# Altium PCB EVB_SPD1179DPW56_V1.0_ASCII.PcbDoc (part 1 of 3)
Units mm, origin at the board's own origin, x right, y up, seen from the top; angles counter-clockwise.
Board outline 135 x 90 mm, 4 copper layers (Top Layer, GND, L3, Bottom Layer), stack 0.603 mm thick; 336 components, 177 nets, 814 pads, 1056 vias.
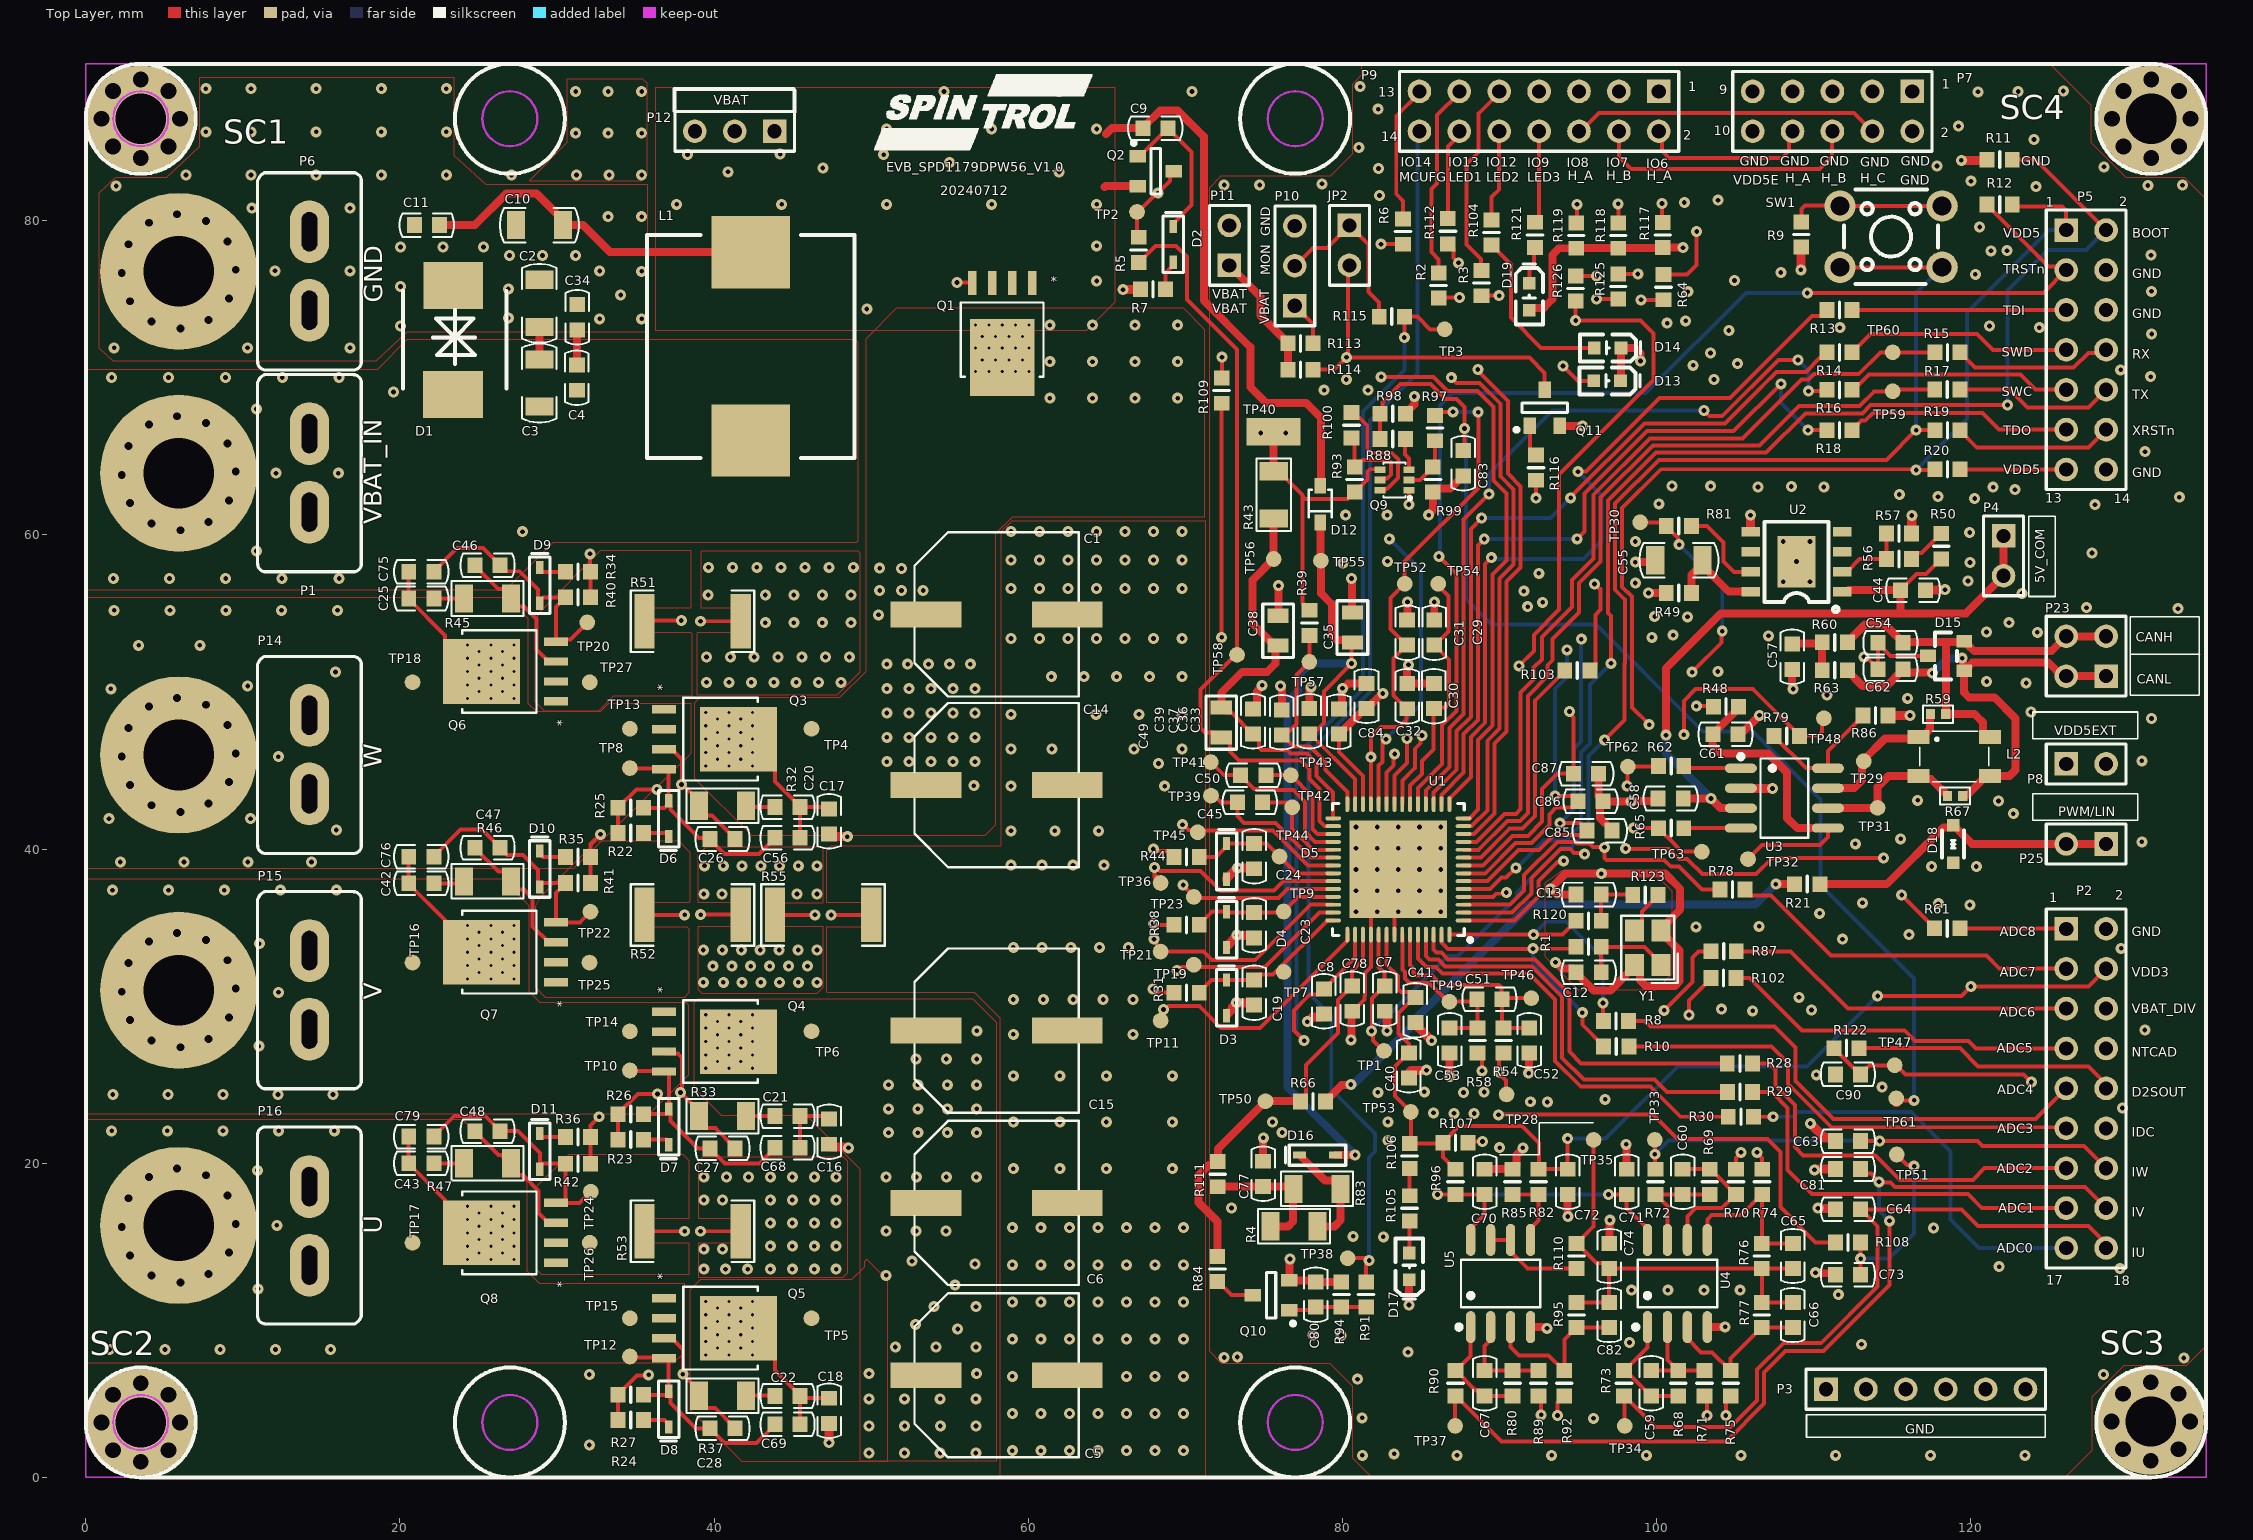
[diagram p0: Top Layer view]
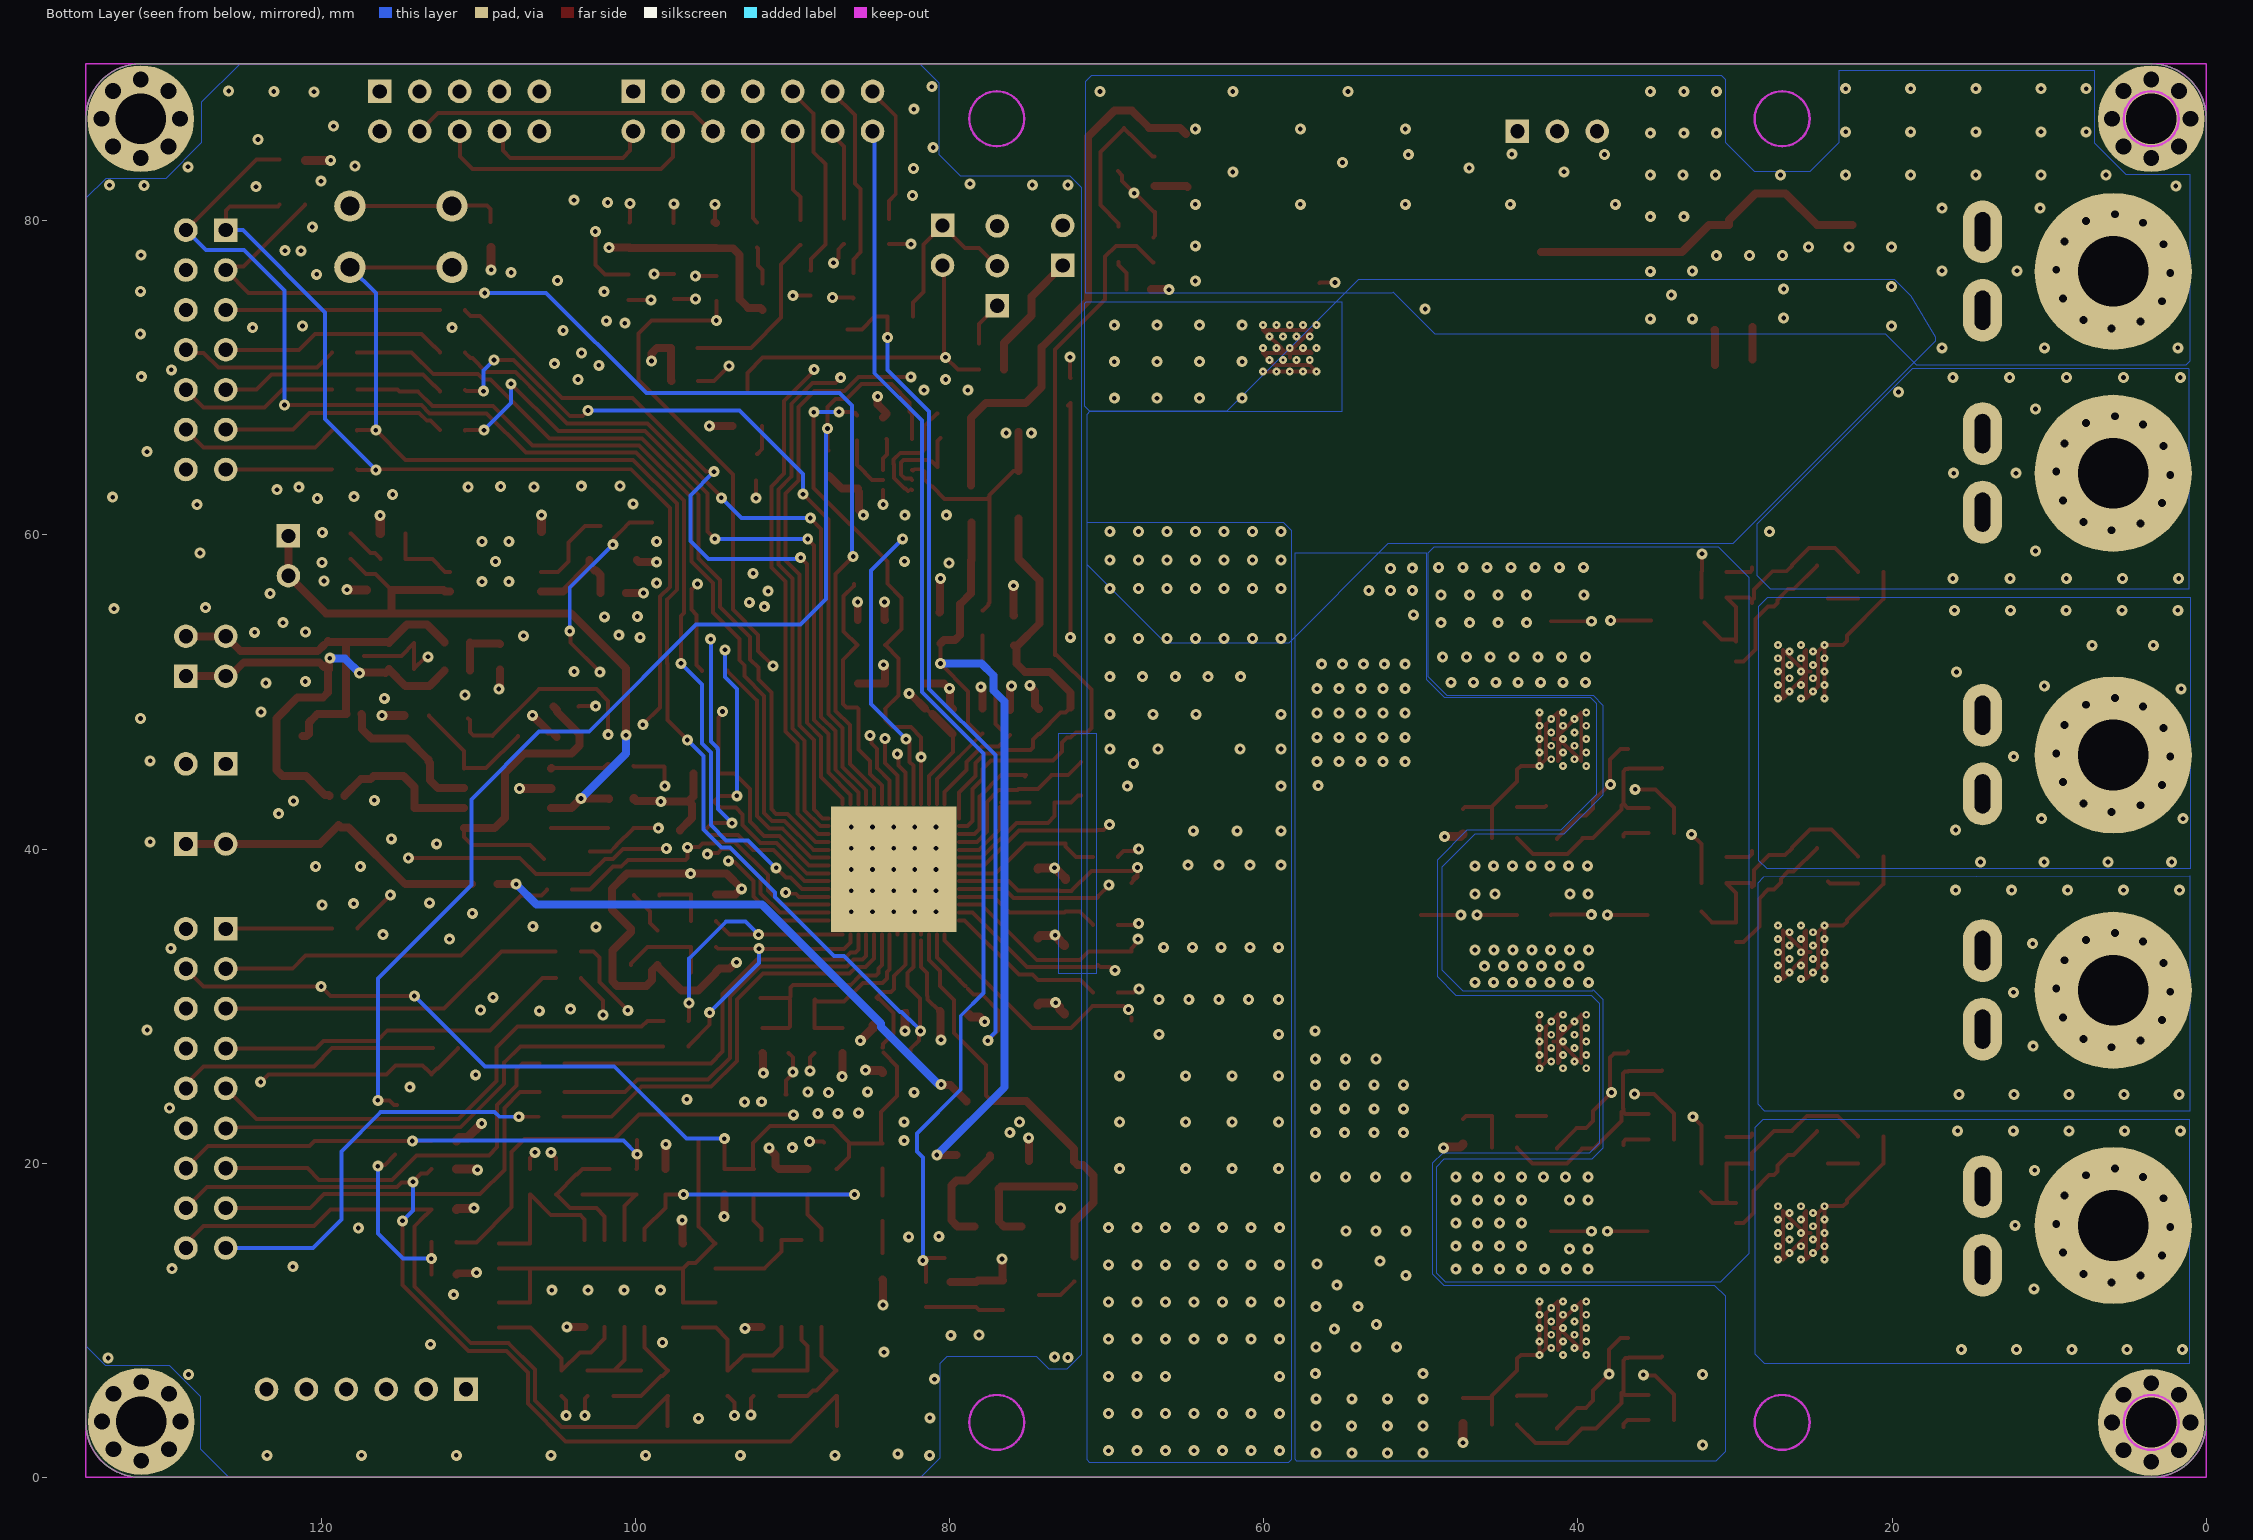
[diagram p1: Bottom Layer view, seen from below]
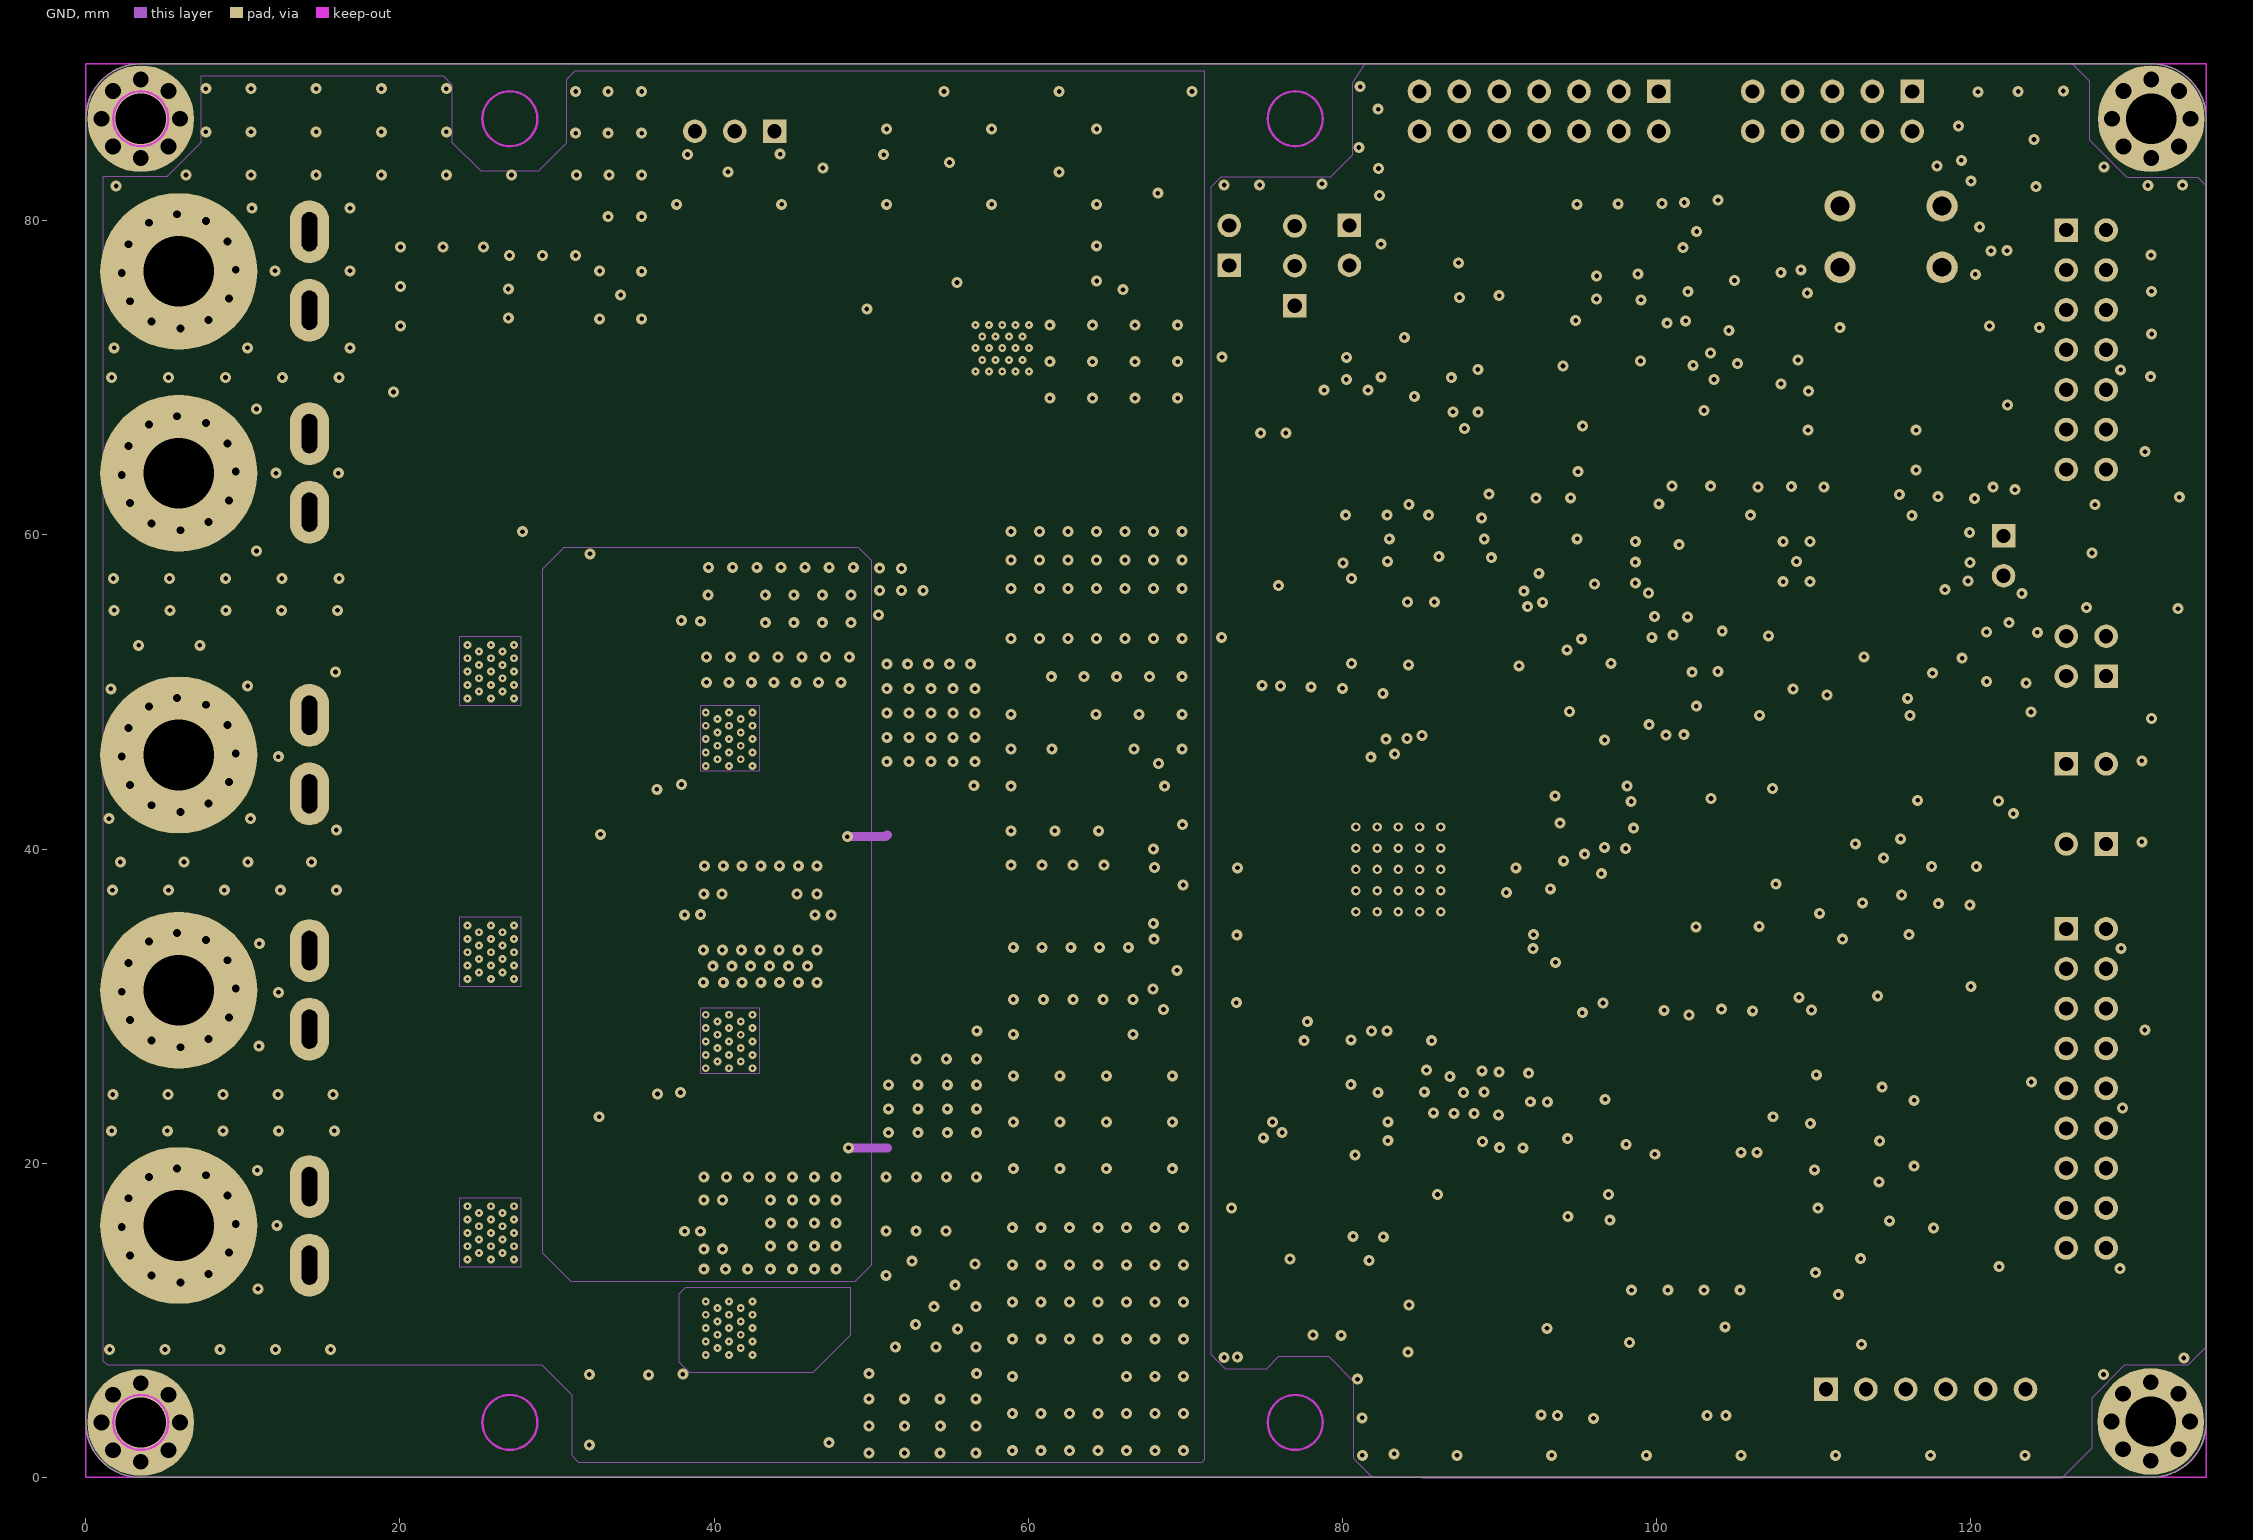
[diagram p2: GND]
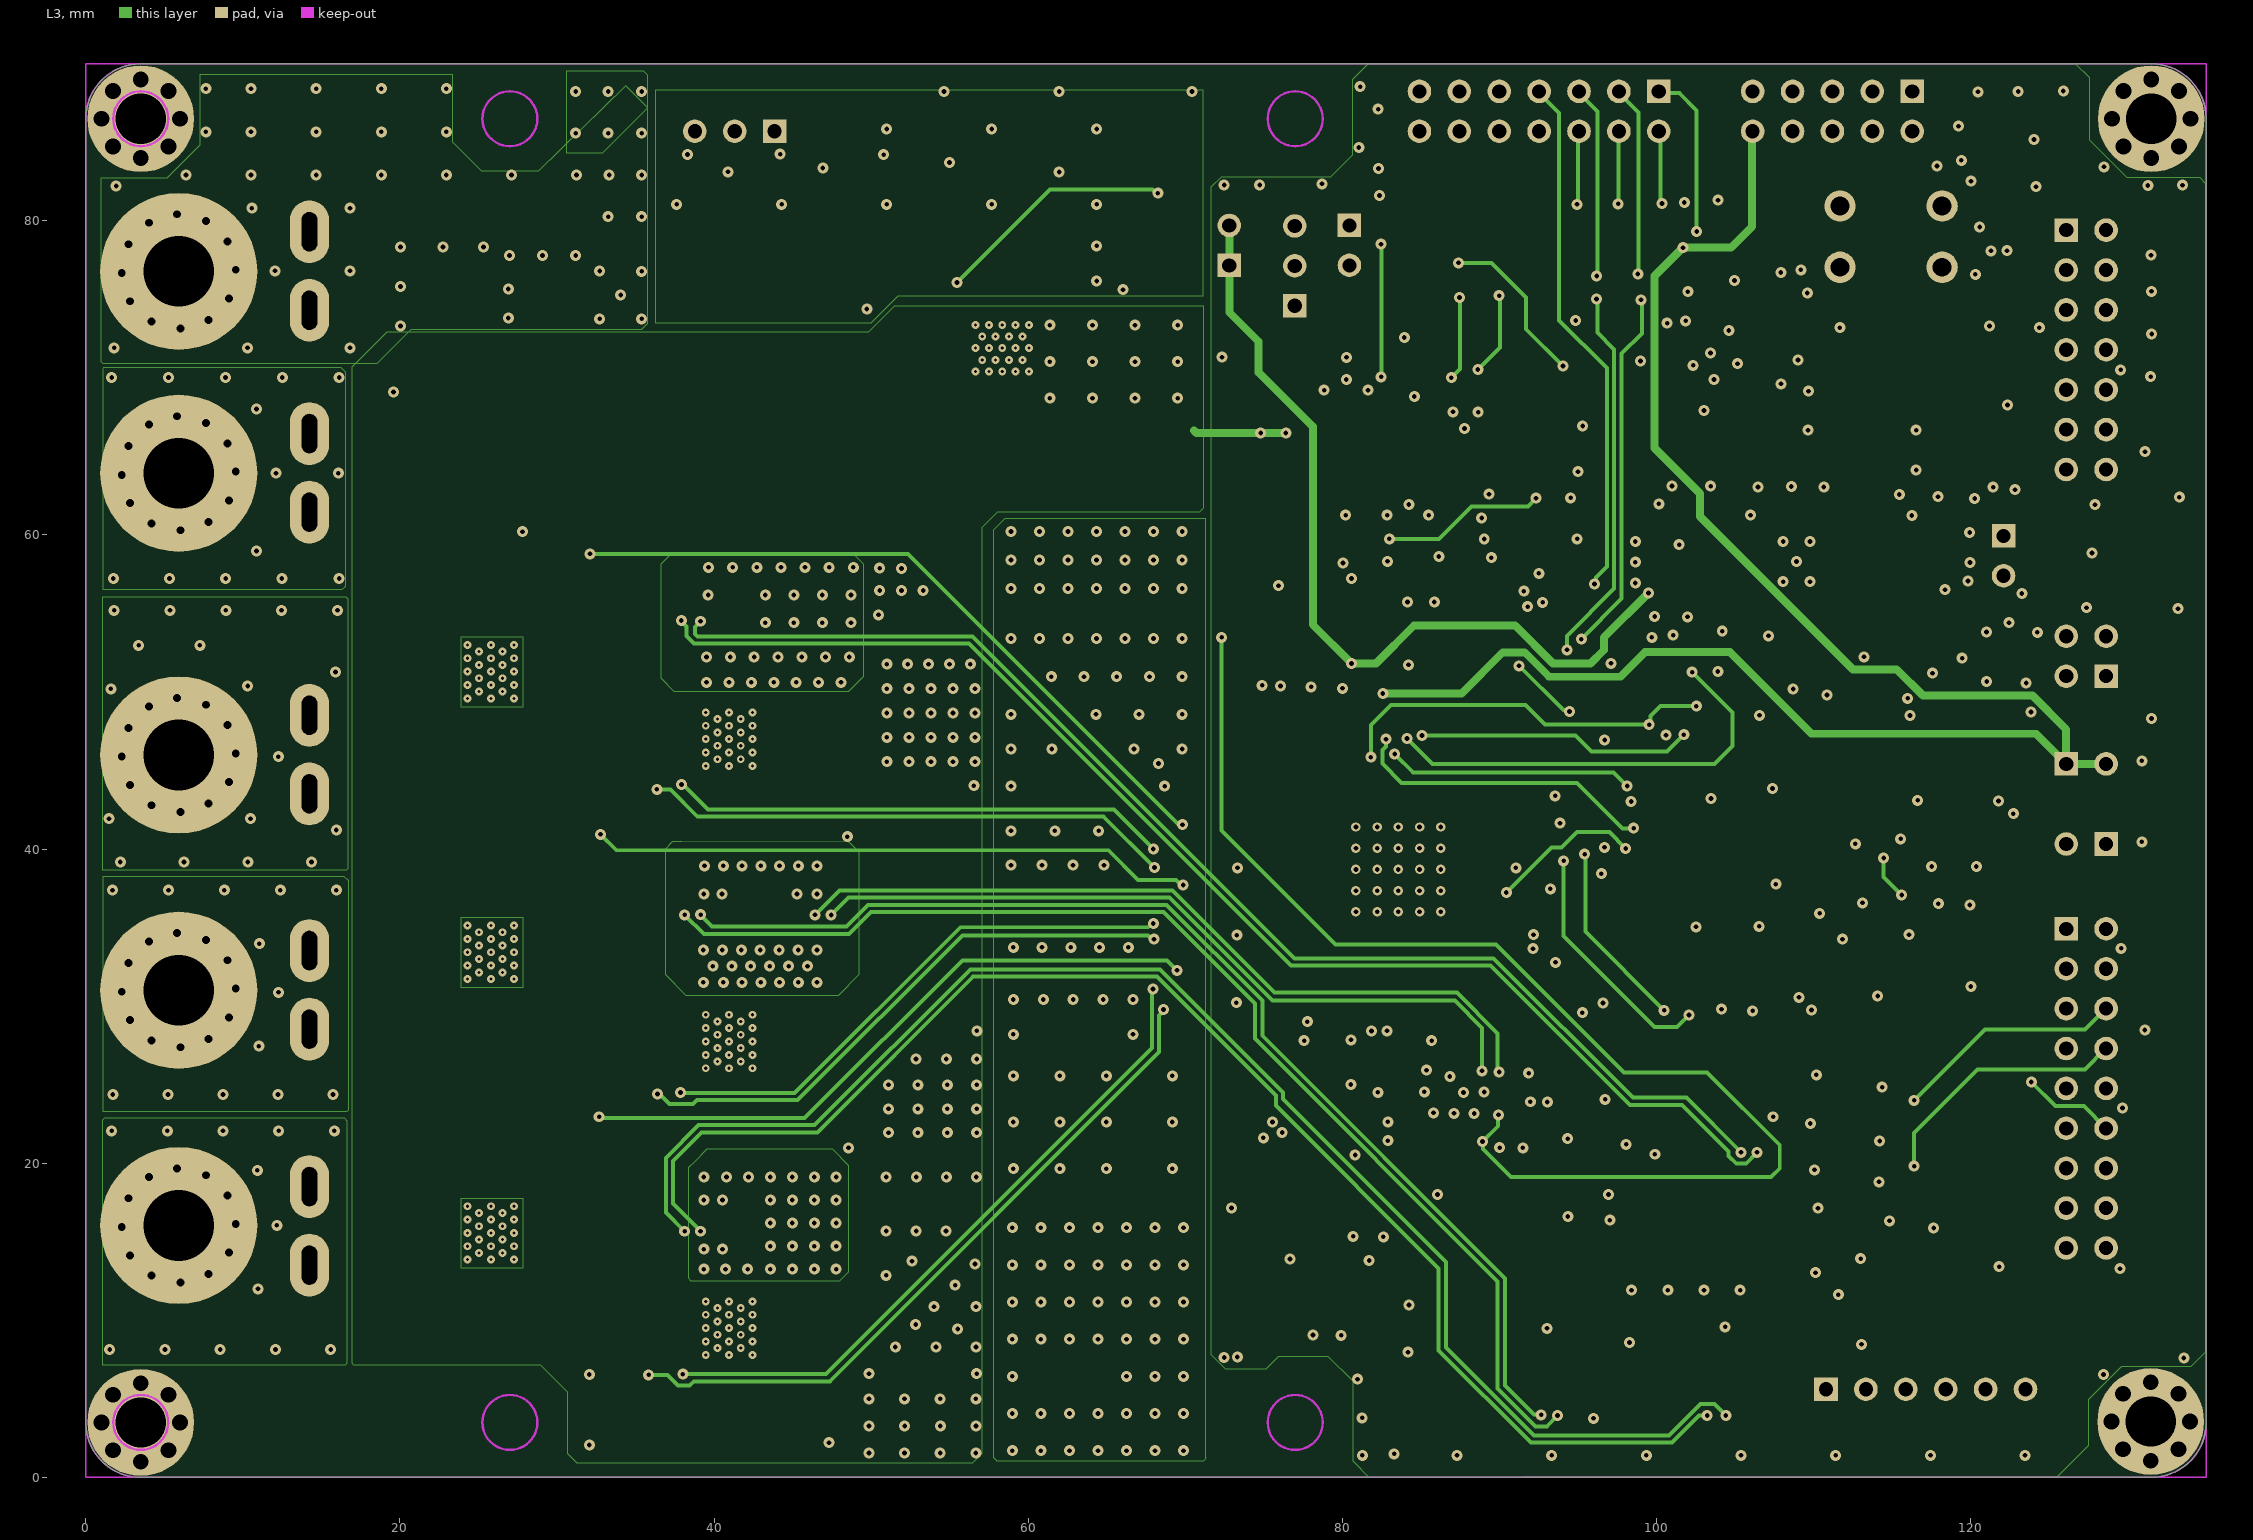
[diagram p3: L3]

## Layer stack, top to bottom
Top Solder: solder mask 0.0102, Solder Resist, Dk 3.5
Top Layer: signal copper 0.0356
Dielectric 2: prepreg 0.0711, PP-006, Dk 4.1
GND: signal copper 0.035
Dielectric 1: dielectric 0.32, FR-4, Dk 4.8
L3: signal copper 0.035
Dielectric 3: prepreg 0.0711, PP-006, Dk 4.1
Bottom Layer: signal copper 0.0356
Bottom Solder: solder mask 0.0102, Solder Resist, Dk 3.5

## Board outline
0,3.448 0,86.5 cw(c3.5,86.5) 3.448,90 131.5,90 cw(c131.5,86.5) 135,86.552 135,3.5 cw(c131.5,3.5) 131.552,0 3.5,0 cw(c3.5,3.5)

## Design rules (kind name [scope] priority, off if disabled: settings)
AssemblyTestPointUsage [All] p0: scope1count=1 scope1_0_kind=Board scope1_0_value=Board scope2count=1 scope2_0_kind=Board scope2_0_value=Board commentlength=0
AssemblyTestpoint [All] p0: scope1count=1 scope1_0_kind=Board scope1_0_value=Board scope2count=1 scope2_0_kind=Board scope2_0_value=Board commentlength=0
BoardOutlineClearance [All] p0: scope1count=1 scope1_0_kind=Board scope1_0_value=Board scope2count=1 scope2_0_kind=Board scope2_0_value=Board commentlength=0 gap=1
BoardOutlineClearance [All] p1: gap=1 ignorepadtopadclearanceinfootprint=FALSE
Clearance [All] p0: scope1count=1 scope1_0_kind=Board scope1_0_value=Board scope2count=1 scope2_0_kind=Board scope2_0_value=Board commentlength=0 gap=0.2
Clearance [All] p1: gap=0.2 ignorepadtopadclearanceinfootprint=FALSE except(0: Arc-Hole Track-Hole SMDPad-Hole THPad-Hole Via-Hole Fill-Hole Poly-Hole Region-Hole Text-Hole)
ComponentClearance [All] p0: scope1count=1 scope1_0_kind=Board scope1_0_value=Board scope2count=1 scope2_0_kind=Board scope2_0_value=Board commentlength=0 gap=0.05 collisioncheckmode=3
ComponentClearance [All] p1: gap=0.05 collisioncheckmode=3 verticalgap=0.05 showdistances=FALSE
DiffPairsRouting [All] p0: scope1count=1 scope1_0_kind=Board scope1_0_value=Board scope2count=1 scope2_0_kind=Board scope2_0_value=Board commentlength=0
FabricationTestPointUsage [All] p0: scope1count=1 scope1_0_kind=Board scope1_0_value=Board scope2count=1 scope2_0_kind=Board scope2_0_value=Board commentlength=0 valid=0 allowmultiple=FALSE
FabricationTestpoint [All] p0: scope1count=1 scope1_0_kind=Board scope1_0_value=Board scope2count=1 scope2_0_kind=Board scope2_0_value=Board commentlength=0 side=3 testpointundercomponent=TRUE minsize=1.016 maxsize=2.54 preferedsize=1.524 minholesize=0 maxholesize=1.016 preferedholesize=0.813 testpointgrid=0.025
FanoutControl Fanout_Default [All] p0: scope1count=1 scope1_0_kind=Board scope1_0_value=Board scope2count=1 scope2_0_kind=Board scope2_0_value=Board commentlength=30 // Fanout_Default (Default Rule)
FanoutControl Fanout_Small [All] p0 off: scope1count=1 scope1_0_kind=Board scope1_0_value=Board scope2count=1 scope2_0_kind=Board scope2_0_value=Board commentlength=84 // Protel DXP Scope 1 Expression Was: (CompPinCount < 5)   Fanout_Small (Default Rule)
FanoutControl Fanout_SOIC [All] p0 off: scope1count=1 scope1_0_kind=Board scope1_0_value=Board scope2count=1 scope2_0_kind=Board scope2_0_value=Board commentlength=71 // Protel DXP Scope 1 Expression Was: IsSOIC   Fanout_SOIC (Default Rule)
FanoutControl Fanout_LCC [All] p0 off: scope1count=1 scope1_0_kind=Board scope1_0_value=Board scope2count=1 scope2_0_kind=Board scope2_0_value=Board commentlength=69 // Protel DXP Scope 1 Expression Was: IsLCC   Fanout_LCC (Default Rule)
FanoutControl Fanout_BGA [All] p0 off: scope1count=1 scope1_0_kind=Board scope1_0_value=Board scope2count=1 scope2_0_kind=Board scope2_0_value=Board commentlength=69 // Protel DXP Scope 1 Expression Was: IsBGA   Fanout_BGA (Default Rule)
Height [All] p0: scope1count=1 scope1_0_kind=Board scope1_0_value=Board scope2count=1 scope2_0_kind=Board scope2_0_value=Board commentlength=0
HoleSize [All] p0: scope1count=1 scope1_0_kind=Board scope1_0_value=Board scope2count=1 scope2_0_kind=Board scope2_0_value=Board commentlength=0 absolutevalues=TRUE maxlimit=10 minlimit=0.025 maxpercent=80.000 minpercent=20.000
HoleSize [All] p1: absolutevalues=TRUE maxlimit=10 minlimit=0.025 maxpercent=80.000 minpercent=20.000
HoleToHoleClearance [All] p0: scope1count=1 scope1_0_kind=Board scope1_0_value=Board scope2count=1 scope2_0_kind=Board scope2_0_value=Board commentlength=0
HoleToHoleClearance [All] p1: gap=0 allowstackedmicrovias=TRUE
LayerPairs [All] p0: scope1count=1 scope1_0_kind=Board scope1_0_value=Board scope2count=1 scope2_0_kind=Board scope2_0_value=Board commentlength=0 enforce=TRUE
MinimumSolderMaskSliver [All] p0: scope1count=1 scope1_0_kind=Board scope1_0_value=Board scope2count=1 scope2_0_kind=Board scope2_0_value=Board commentlength=0
MinimumSolderMaskSliver [All] p1: minsoldermaskwidth=0
NetAntennae [All] p0: scope1count=1 scope1_0_kind=Board scope1_0_value=Board scope2count=1 scope2_0_kind=Board scope2_0_value=Board commentlength=0
PasteMaskExpansion [All] p0: scope1count=1 scope1_0_kind=Board scope1_0_value=Board scope2count=1 scope2_0_kind=Board scope2_0_value=Board commentlength=0 expansion=0
PlaneClearance [All] p0: scope1count=1 scope1_0_kind=Board scope1_0_value=Board scope2count=1 scope2_0_kind=Board scope2_0_value=Board commentlength=0 clearance=0.508
PlaneConnect [All] p0: scope1count=1 scope1_0_kind=Board scope1_0_value=Board scope2count=1 scope2_0_kind=Board scope2_0_value=Board commentlength=0 planeconnectstyle=Relief reliefexpansion=0.508 reliefentries=4 reliefconductorwidth=0.254 reliefairgap=0.254
PolygonConnect GND [All] p0 off: scope1count=1 scope1_0_kind=Board scope1_0_value=Board scope2count=1 scope2_0_kind=Board scope2_0_value=Board commentlength=57 connectstyle=Direct reliefconductorwidth=0.5 reliefentries=4 polygonreliefangle="90 Angle" // Protel DXP Scope 2 Expression Was: All And  Not IsVia
PolygonConnect [All] p0: scope1count=1 scope1_0_kind=Board scope1_0_value=Board scope2count=1 scope2_0_kind=Board scope2_0_value=Board commentlength=0 connectstyle=Direct reliefconductorwidth=0.254 reliefentries=4 polygonreliefangle="45 Angle"
PolygonConnect GND [IsNamedPolygon('GND') And InNet('GND') vs All And  Not IsVia] p1: connectstyle=Direct reliefconductorwidth=0.5 reliefentries=4 polygonreliefangle="90 Angle" airgapwidth=0.3
PolygonConnect [All] p2: connectstyle=Direct reliefconductorwidth=0.254 reliefentries=4 polygonreliefangle="45 Angle" airgapwidth=0.254
RoutingCorners [All] p0: scope1count=1 scope1_0_kind=Board scope1_0_value=Board scope2count=1 scope2_0_kind=Board scope2_0_value=Board commentlength=0 cornerstyle=45-Degree minsetback=2.54 maxsetback=2.54
RoutingLayers [All] p0: scope1count=1 scope1_0_kind=Board scope1_0_value=Board scope2count=1 scope2_0_kind=Board scope2_0_value=Board commentlength=0 top layer=Automatic mid layer 1=Automatic mid layer 2=Automatic bottom layer=Automatic
RoutingPriority [All] p0: scope1count=1 scope1_0_kind=Board scope1_0_value=Board scope2count=1 scope2_0_kind=Board scope2_0_value=Board commentlength=0
RoutingTopology [All] p0: scope1count=1 scope1_0_kind=Board scope1_0_value=Board scope2count=1 scope2_0_kind=Board scope2_0_value=Board commentlength=0 topology=Shortest
RoutingVias [All] p0: scope1count=1 scope1_0_kind=Board scope1_0_value=Board scope2count=1 scope2_0_kind=Board scope2_0_value=Board commentlength=0 holewidth=0.711 width=1.27 viastyle="Through Hole" minholewidth=0.711 minwidth=1.27 maxholewidth=0.711 maxwidth=1.27
RoutingVias [All] p1: holewidth=0.711 width=1.27 viastyle="Through Hole" minholewidth=0.711 minwidth=1.27 maxholewidth=0.711 maxwidth=1.27
ShortCircuit [All] p0: scope1count=1 scope1_0_kind=Board scope1_0_value=Board scope2count=1 scope2_0_kind=Board scope2_0_value=Board commentlength=0 allowed=FALSE
SilkToBoardRegionClearance [All] p0: scope1count=1 scope1_0_kind=Board scope1_0_value=Board scope2count=1 scope2_0_kind=Board scope2_0_value=Board commentlength=0
SilkToSilkClearance [All] p0 off: scope1count=1 scope1_0_kind=Board scope1_0_value=Board scope2count=1 scope2_0_kind=Board scope2_0_value=Board commentlength=0
SilkToSilkClearance [All] p1 off: silktosilkclearance=0
SilkToSolderMaskClearance [All] p0 off: scope1count=1 scope1_0_kind=Board scope1_0_value=Board scope2count=1 scope2_0_kind=Board scope2_0_value=Board commentlength=44 // Protel DXP Scope 1 Expression Was: IsPad
SilkToSolderMaskClearance [IsPad] p1: minsilkscreentomaskgap=0 clearancetoexposedcopper=TRUE
SolderMaskExpansion [All] p0: scope1count=1 scope1_0_kind=Board scope1_0_value=Board scope2count=1 scope2_0_kind=Board scope2_0_value=Board commentlength=0 expansion=0.102
SolderMaskExpansion [All] p1: expansion=0.102 istentingtop=FALSE
UnRoutedNet [All] p0: scope1count=1 scope1_0_kind=Board scope1_0_value=Board scope2count=1 scope2_0_kind=Board scope2_0_value=Board commentlength=0
UnpouredPolygon [All] p0: scope1count=1 scope1_0_kind=Board scope1_0_value=Board scope2count=1 scope2_0_kind=Board scope2_0_value=Board commentlength=0
Width [All] p0: scope1count=1 scope1_0_kind=Board scope1_0_value=Board scope2count=1 scope2_0_kind=Board scope2_0_value=Board commentlength=0 maxlimit=2.54 minlimit=0.203 preferedwidth=0.254
Width [All] p1: maxlimit=2.54 minlimit=0.203 preferedwidth=0.254
24 further rules are at their usual default settings.

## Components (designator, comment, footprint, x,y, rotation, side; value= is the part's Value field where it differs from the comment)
C1 "EEHZK1E471P" CAP-SMD_BD10.0-L10.3-W10.3-FD 57.988,54.947 r0 top
C2 "CAP" C1206 28.88,74.752 r270 top
C3 "CAP" C1206 28.88,69.672 r270 top
C4 "CAP" C0603 31.267,70.015 r270 top
C5 "EEHZK1E471P" CAP-SMD_BD10.0-L10.3-W10.3-FD 57.988,6.502 r0 top
C6 "EEHZK1E471P" CAP-SMD_BD10.0-L10.3-W10.3-FD 57.988,17.475 r0 top
C7 "CAP" C0603 82.703,30.48 r90 top
C8 "CAP" C0603 78.829,30.306 r90 top
C9 "CAP" C0603 68.097,85.903 r180 top
C10 "CAP" C1206 28.88,79.731 r180 top
C11 "CAP" C0603 21.717,79.731 r0 top
C12 "CAP" C0603 95.682,32.156 r0 top
C13 "CAP" C0603 95.682,37.109 r0 top
C14 "EEHZK1E471P" CAP-SMD_BD10.0-L10.3-W10.3-FD 57.988,44.076 r0 top
C15 "EEHZK1E471P" CAP-SMD_BD10.0-L10.3-W10.3-FD 57.988,28.448 r0 top
C16 "CAP" C0603 47.32,22.012 r90 top
C17 "CAP" C0603 47.32,41.764 r90 top
C18 "CAP" C0603 47.32,4.242 r90 top
C19 "NC" C0603 74.381,30.864 r90 top
C20 "CAP" C0603 44.679,42.679 r0 top
C21 "CAP" C0603 44.679,23.003 r0 top
C22 "CAP" C0603 44.679,5.182 r0 top
C23 "NC" C0603 74.381,35.154 r90 top
C24 "NC" C0603 74.381,39.551 r90 top
C25 "CAP" C0603 21.361,55.956 r180 top
C26 "CAP" C0603 40.538,40.647 r180 top
C27 "CAP" C0603 40.538,20.946 r180 top
C28 "CAP" C0603 40.538,3.124 r180 top
C29 "CAP" C0603 85.852,53.784 r270 top
C30 "CAP" C0603 85.833,49.742 r270 top
C31 "CAP" C0603 84.122,53.784 r270 top
C32 "CAP" C0603 84.128,49.737 r270 top
C33 "CAP" C0603 79.785,48.122 r270 top
C34 "CAP" C0603 31.293,73.863 r270 top
C35 "CAP" 0805R 80.642,55.06 r270 top
C36 "CAP" C0603 77.9,48.147 r270 top
C37 "CAP" C0603 76.144,48.068 r270 top
C38 "CAP" 0805R 75.908,54.861 r270 top
C39 "CAP" C0603 74.312,48.134 r270 top
C40 "CAP" C0603 84.242,26.228 r90 top
C41 "CAP" C0603 84.653,29.753 r90 top
C42 "CAP" C0603 21.361,37.819 r180 top
C43 "CAP" C0603 21.361,19.998 r180 top
C44 "CAP" C0603 116.332,56.49 r180 top
C45 "CAP" C0603 74.115,42.977 r180 top
C46 "CAP" C0603 25.578,58.064 r0 top
C47 "CAP" C0603 25.578,40.08 r0 top
C48 "CAP" C0603 25.578,22.047 r0 top
C49 "CAP" 0805R 72.292,47.109 r90 top
C50 "CAP" C0603 74.33,44.704 r0 top
C51 "CAP" C0603 89.367,30.437 r0 top
C52 "CAP" C0603 91.907,27.821 r90 top
C53 "CAP" C0603 86.827,27.821 r90 top
C54 "CAP" C0603 114.897,53.137 r0 top
C55 "CAP" C1206 101.422,58.395 r0 top
C56 "NC" C0603 44.679,40.723 r180 top
C57 "CAP" C0603 108.636,52.248 r90 top
C58 "CAP" C0603 100.904,43.222 r0 top
C59 "CAP" C0603 99.662,5.994 r90 top
C60 "CAP" C0603 101.662,18.821 r90 top
C61 "CAP" C0603 104.394,47.32 r180 top
C62 "CAP" C0603 114.897,51.46 r0 top
C63 "CAP" C0603 112.192,21.412 r0 top
C64 "CAP" C0603 112.192,17.069 r0 top
C65 "CAP" C0603 108.687,14.097 r90 top
C66 "CAP" C0603 108.687,10.338 r270 top
C67 "CAP" C0603 89.057,5.994 r90 top
C68 "NC" C0603 44.679,20.996 r180 top
C69 "NC" C0603 44.679,3.378 r180 top
C70 "CAP" C0603 89.057,18.821 r270 top
C71 "CAP" C0603 98.106,18.821 r270 top
C72 "CAP" C0603 94.345,18.821 r90 top
C73 "CAP" C0603 112.192,12.903 r0 top
C74 "CAP" C0603 96.987,14.097 r270 top
C75 "NC" C0603 21.361,57.658 r0 top
C76 "NC" C0603 21.361,39.521 r0 top
C77 "CAP" C0603 74.955,19.329 r270 top
C78 "CAP" C0603 80.629,30.48 r90 top
C79 "NC" C0603 21.361,21.7 r0 top
C80 "CAP" C0603 78.313,11.637 r270 top
C81 "CAP" C0603 112.192,19.634 r0 top
C82 "CAP" C0603 96.987,10.338 r270 top
C83 "CAP" C0603 87.701,64.568 r90 top
C84 "CAP" C0603 81.538,49.75 r270 top
C85 "CAP" C0603 96.381,41.18 r0 top
C86 "CAP" C0603 95.808,43.042 r180 top
C87 "CAP" C0603 95.521,44.803 r0 top
C90 "CAP" C0603 112.192,25.654 r0 top
D1 "" SMC/DO-214AB/Bidirect 23.495,72.593 r90 top
D2 "DIODE" SODFL2513X100/SOD323F/SC-90 69.24,78.508 r270 top
D3 "NC" SODFL2513X100/SOD323F/SC-90 72.628,30.531 r270 top
D4 "NC" SODFL2513X100/SOD323F/SC-90 72.628,34.874 r270 top
D5 "NC" SODFL2513X100/SOD323F/SC-90 72.628,39.218 r270 top
D6 "" SODFL2513X100/SOD323F/SC-90 37.109,41.942 r90 top
D7 "" SODFL2513X100/SOD323F/SC-90 37.109,22.317 r90 top
D8 "" SODFL2513X100/SOD323F/SC-90 37.109,4.343 r90 top
D9 "" SODFL2513X100/SOD323F/SC-90 28.905,56.794 r270 top
D10 "" SODFL2513X100/SOD323F/SC-90 28.905,38.737 r270 top
D11 "" SODFL2513X100/SOD323F/SC-90 28.905,20.76 r270 top
D12 "DIODE" SOD-323_L1.8-W1.3-LS2.5-RD 78.595,61.971 r90 top
D13 "D_LED_0603" LED0603-R-RD 96.86,69.809 r180 top
D14 "D_LED_0603" LED0603-R-RD 96.892,71.905 r180 top
D15 "PESD1CAN,215" SOT-23_L2.9-W1.3-P1.90-LS2.4-BR 118.44,52.299 r0 top
D16 "" SODFL2513X100/SOD323F/SC-90 78.419,20.523 r0 top
D17 "D_LED_0603" LED0603-R-RD 84.261,13.437 r90 top
D18 "TVS" SOD-323_L1.7-W1.3-LS2.5-BI 118.897,40.327 r90 top
D19 "D_LED_0603" LED0603-R-RD 91.905,75.171 r270 top
JP2 "open" HDR1X2 80.452,79.708 r270 top
L1 "1uH 40A" IND-SMD_L12.6-W13.5 42.342,72.009 r90 top
L2 "ACT45B-510-2P-TL003" IND-SMD_4P-L4.5-W3.2-TL 118.949,45.897 r0 top
P1 "P_CON-1PIN" CON_63X08_P1 14.24,66.457 r270 top
P2 "Header 9X2" HDR2X9 126.086,34.925 r270 top
P3 "Header 6" HDR1X6 110.795,5.613 r0 top
P4 "" HDR1X2 122.098,59.944 r270 top
P5 "Header 7X2" HDR2X7 126.086,79.41 r270 top
P6 "P_CON-1PIN" CON_63X08_P1 14.24,79.309 r270 top
P7 "Header 5X2" HDR2X5 116.282,88.244 r180 top
P8 "" HDR1X2 126.086,45.425 r0 top
P9 "Header 7X2" HDR2X7 100.149,88.244 r180 top
P10 "Header 3" HDR1X3 76.974,74.596 r90 top
P11 "" HDR1X2 72.803,77.168 r90 top
P12 "Header 3" HDR1X3 43.855,85.704 r180 top
P14 "P_CON-1PIN" CON_63X08_P1 14.24,48.518 r270 top
P15 "P_CON-1PIN" CON_63X08_P1 14.24,33.542 r270 top
P16 "P_CON-1PIN" CON_63X08_P1 14.24,13.517 r90 top
P23 "Header 2X2" HDR2X2 128.626,51.013 r90 top
P25 "Header 2" HDR1X2 128.626,40.327 r180 top
Q1 "SQJ138EP" PowerPAK_SO-8L_3_VIS 58.344,72.441 r180 top
Q2 "NPN" SOT95P240X110-3/SOT23/TO-236 68.123,83.16 r0 top
Q3 "SQJ138EP" PowerPAK_SO-8L_3_VIS 40.411,46.997 r270 top
Q4 "SQJ138EP" PowerPAK_SO-8L_3_VIS 40.411,27.748 r270 top
Q5 "SQJ138EP" PowerPAK_SO-8L_3_VIS 40.411,9.5 r270 top
Q6 "SQJ138EP" PowerPAK_SO-8L_3_VIS 26.333,51.308 r90 top
Q7 "SQJ138EP" PowerPAK_SO-8L_3_VIS 26.333,33.439 r90 top
Q8 "SQJ138EP" PowerPAK_SO-8L_3_VIS 26.333,15.57 r90 top
Q9 "BC847BPN,115" SOT-363_L2.0-W1.3-P0.65-LS2.1-TL 83.312,63.5 r180 top
Q10 "NPN" SOT95P240X110-3/SOT23/TO-236 75.461,11.601 r180 top
Q11 "MOSFET_N-CH" SOT95P240X110-3/SOT23/TO-236 92.885,68.097 r90 top
R1 "NC" R0603 95.682,33.782 r180 top
R2 "RES" R0603 86.133,75.888 r270 top
R3 "RES" R0603 88.857,76.033 r270 top
R4 "" R1206 76.922,15.983 r0 top
R5 "RES" R0603 67.031,78.156 r90 top
R6 "RES" R0603 83.861,79.312 r270 top
R7 "RES" R0603 67.945,75.641 r0 top
R8 "RES" R0603 97.429,29.064 r180 top
R9 "RES" R0603 109.22,79.129 r270 top
R10 "RES" R0603 97.439,27.433 r180 top
R11 "RES" R0603 121.852,83.897 r0 top
R12 "RES" R0603 121.852,81.045 r0 top
R13 "RES" R0603 111.658,74.32 r180 top
R14 "RES" R0603 111.658,71.628 r180 top
R15 "RES" R0603 118.529,71.628 r0 top
R16 "RES" R0603 111.658,69.24 r180 top
R17 "RES" R0603 118.516,69.266 r0 top
R18 "RES" R0603 111.658,66.667 r180 top
R19 "RES" R0603 118.529,66.667 r0 top
R20 "RES" R0603 118.529,64.186 r180 top
R21 "RES" R0603 109.601,37.77 r180 top
R22 "" R0603 34.696,41.028 r180 top
R23 "" R0603 34.696,21.504 r180 top
R24 "" R0603 34.696,3.658 r180 top
R25 "" R0603 34.696,42.628 r180 top
R26 "" R0603 34.696,23.13 r180 top
R27 "" R0603 34.696,5.258 r180 top
R28 "RES" R0603 105.308,26.352 r180 top
R29 "RES" R0603 105.321,24.536 r180 top
R30 "RES" R0603 105.372,22.962 r180 top
R31 "RES" R0603 70.088,30.861 r0 top
R32 "RES" R1206 40.538,42.755 r180 top
R33 "RES" R1206 40.538,23.003 r180 top
R34 "" R0603 31.344,57.658 r0 top
R35 "" R0603 31.344,39.496 r0 top
R36 "" R0603 31.344,21.674 r0 top
R37 "RES" R1206 40.538,5.207 r180 top
R38 "RES" R0603 70.088,35.179 r0 top
R39 "" R0603 77.911,54.407 r90 top
R40 "" R0603 31.344,56.032 r0 top
R41 "" R0603 31.344,37.845 r0 top
R42 "" R0603 31.344,19.972 r0 top
R43 "RES" R1206 75.625,62.56 r270 top
R44 "RES" R0603 70.088,39.497 r0 top
R45 "RES" R1206 25.578,55.956 r0 top
R46 "RES" R1206 25.578,37.946 r0 top
R47 "RES" R1206 25.578,19.998 r0 top
R48 "RES" R0603 104.419,49.073 r180 top
R49 "RES" R0603 101.422,56.312 r0 top
R50 "RES" R0603 118.135,59.284 r270 top
R51 "RES" R2512 38.633,54.508 r180 top
R52 "RES" R2512 38.633,35.814 r180 top
R53 "RES" R2512 38.633,15.672 r180 top
R54 "RES" R0603 90.256,27.821 r90 top
R55 "RES" R2512 46.939,35.814 r180 top
R56 "RES" R0603 115.443,58.471 r0 top
R57 "RES" R0603 115.443,60.096 r180 top
R58 "RES" R0603 88.605,27.821 r90 top
R59 "NC" R0402 117.929,48.594 r0 top
R60 "RES" R0603 111.354,53.162 r0 top
R61 "RES" R0603 118.512,34.954 r180 top
R62 "RES" R0603 100.937,45.296 r180 top
R63 "RES" R0603 111.354,51.384 r0 top
R64 "RES" R0603 100.448,75.775 r270 top
R65 "RES" R0603 100.937,41.336 r180 top
R66 "磁珠" R0603 78.13,23.927 r180 top
R67 "NC" R0402 119.012,43.387 r0 top
R68 "RES" R0603 101.389,5.994 r90 top
R69 "RES" R0603 103.389,18.821 r90 top
R70 "RES" R0603 105.057,18.821 r90 top
R71 "RES" R0603 103.057,5.994 r270 top
R72 "RES" R0603 99.935,18.821 r270 top
R73 "RES" R0603 97.935,5.994 r90 top
R74 "RES" R0603 106.725,18.821 r90 top
R75 "RES" R0603 104.725,5.994 r270 top
R76 "RES" R0603 106.705,14.097 r90 top
R77 "RES" R0603 106.705,10.338 r270 top
R78 "RES" R0603 104.834,37.424 r180 top
R79 "RES" R0603 108.294,47.201 r180 top
R80 "RES" R0603 90.84,5.994 r90 top
R81 "RES" R0603 101.422,60.579 r0 top
R82 "RES" R0603 92.491,18.821 r270 top
R83 "" R1206 78.384,18.364 r0 top
R84 "NC" R0603 72.044,13.275 r270 top
R85 "RES" R0603 90.84,18.821 r90 top
R86 "RES" R0603 113.949,48.514 r180 top
R87 "RES" R0603 104.281,33.496 r180 top
R88 "RES" R0603 83.21,66.116 r0 top
R89 "RES" R0603 92.491,5.994 r270 top
R90 "RES" R0603 87.208,5.994 r90 top
R91 "RES" R0603 81.513,11.637 r90 top
R92 "RES" R0603 94.133,5.994 r270 top
R93 "RES" R0603 80.781,63.528 r90 top
R94 "RES" R0603 79.939,11.637 r270 top
R95 "RES" R0603 94.904,10.338 r270 top
R96 "" R0603 87.208,18.821 r270 top
R97 "RES" R0603 85.902,66.801 r270 top
R98 "RES" R0603 83.21,67.716 r0 top
R99 "RES" R0603 85.765,63.528 r90 top
R100 "RES" R0603 80.579,66.987 r90 top
R102 "RES" R0603 104.267,31.797 r180 top
R103 "RES" R0603 94.96,51.369 r180 top
R104 "RES" R0603 89.499,79.263 r270 top
R105 "RES" R0603 84.287,17.132 r270 top
R106 "RES" R0603 84.287,20.46 r90 top
R107 "RES" R0603 87.198,21.311 r180 top
R108 "RES" R0603 112.192,14.961 r0 top
R109 "NTC" R0603 72.314,69.19 r90 top
R110 "RES" R0603 94.904,14.097 r270 top
R111 "NC" R0603 72.069,19.304 r270 top
R112 "RES" R0603 86.72,79.339 r270 top
R113 "RES" R0603 77.344,72.199 r180 top
R114 "" R0603 77.337,70.524 r0 top
R115 "RES" R0603 83.149,73.903 r180 top
R116 "RES" R0603 92.336,64.283 r90 top
R117 "RES" R0603 100.397,79.099 r270 top
R118 "RES" R0603 97.57,79.058 r270 top
R119 "RES" R0603 94.889,79.056 r270 top
R120 "NC" R0603 95.682,35.433 r180 top
R121 "RES" R0603 92.263,79.109 r270 top
R122 "RES" R0603 112.09,27.33 r0 top
R123 "RES" R0603 99.289,37.084 r180 top
R125 "RES" R0603 97.563,75.819 r270 top
R126 "RES" R0603 94.856,75.694 r270 top
SC1 "SCREW" "SCREW_HOLE_Φ3_plated_wo keepout" 3.5,86.5 r0 top (schematic designator SC?)
SC2 "SCREW" "SCREW_HOLE_Φ3_plated_wo keepout" 3.5,3.5 r0 top (schematic designator SC?)
SC3 "SCREW" "SCREW_HOLE_Φ3_plated_wo keepout" 131.472,3.555 r0 top (schematic designator SC?)
SC4 "SCREW" "SCREW_HOLE_Φ3_plated_wo keepout" 131.5,86.5 r0 top (schematic designator SC?)
SW1 "TS-1095PD-A6B2-D2" KEY-TH_4P-L6.0-W6.0-P3.90-LS6.5 114.935,78.994 r0 top
TP1 "TEST-Point" TP-1.0 82.652,27.153 r0 top
TP2 "TEST-Point" TP-1.0 66.929,80.569 r0 top
TP3 "TEST-Point" TP-1.0 86.511,73.094 r0 top
TP4 "TEST-Point" TP-1.0 46.203,47.66 r0 top
TP5 "TEST-Point" TP-1.0 46.203,10.135 r0 top
TP6 "TEST-Point" TP-1.0 46.203,28.397 r0 top
TP7 "TEST-Point" TP-1.0 76.26,32.182 r0 top
TP8 "TEST-Point" TP-1.0 34.646,45.161 r90 top
TP9 "TEST-Point" TP-1.0 76.26,36.03 r0 top
TP10 "TEST-Point" TP-1.0 34.646,25.908 r90 top
TP11 "TEST-Point" TP-1.0 68.428,29.083 r90 top
TP12 "TEST-Point" TP-1.0 34.646,7.696 r90 top
TP13 "TEST-Point" TP-1.0 34.646,47.66 r90 top
TP14 "TEST-Point" TP-1.0 34.646,28.397 r90 top
TP15 "TEST-Point" TP-1.0 34.646,10.135 r90 top
TP16 "TEST-Point" TP-1.0 20.803,32.779 r180 top
TP17 "TEST-Point" TP-1.0 20.803,14.935 r90 top
TP18 "TEST-Point" TP-1.0 20.803,50.622 r90 top
TP19 "TEST-Point" TP-1.0 70.545,32.639 r180 top
TP20 "TEST-Point" TP-1.0 31.928,54.432 r0 top
TP21 "TEST-Point" TP-1.0 68.428,33.477 r180 top
TP22 "TEST-Point" TP-1.0 32.131,36.017 r90 top
TP23 "TEST-Point" TP-1.0 70.545,36.957 r180 top
TP24 "TEST-Point" TP-1.0 32.156,18.186 r0 top
TP25 "TEST-Point" TP-1.0 32.069,32.779 r90 top
TP26 "TEST-Point" TP-1.0 32.08,14.935 r90 top
TP27 "TEST-Point" TP-1.0 32.08,50.622 r90 top
TP28 "TEST-Point" TP-1.0 90.454,24.383 r90 top
TP29 "TEST-Point" TP-1.0 113.191,45.589 r90 top
TP30 "TEST-Point" TP-1.0 98.958,60.808 r270 top
TP31 "TEST-Point" TP-1.0 114.075,42.626 r90 top
TP32 "TEST-Point" TP-1.0 105.828,39.366 r90 top
TP33 "TEST-Point" TP-1.0 99.898,21.488 r180 top
TP34 "TEST-Point" TP-1.0 97.974,3.277 r180 top
TP35 "TEST-Point" TP-1.0 95.996,21.488 r180 top
TP36 "TEST-Point" TP-1.0 68.428,37.846 r270 top
TP37 "TEST-Point" TP-1.0 87.182,3.277 r90 top
TP38 "TEST-Point" TP-1.0 80.336,13.957 r180 top
TP39 "TEST-Point" TP-1.0 71.637,43.409 r270 top
TP40 "TEST-SMD" TEST-SMD_L2.7-W1.0 75.625,66.573 r0 top
TP41 "TEST-Point" TP-1.0 71.623,45.544 r90 top
TP42 "TEST-Point" TP-1.0 76.806,42.671 r90 top
TP43 "TEST-Point" TP-1.0 76.725,44.707 r90 top
TP44 "TEST-Point" TP-1.0 76,39.531 r90 top
TP45 "TEST-Point" TP-1.0 70.79,41.072 r90 top
TP46 "TEST-Point" TP-1.0 92.034,30.513 r90 top
TP47 "TEST-Point" TP-1.0 115.164,26.238 r90 top
TP48 "TEST-Point" TP-1.0 110.663,48.331 r90 top
TP49 "TEST-Point" TP-1.0 86.818,30.284 r90 top
TP50 "TEST-Point" TP-1.0 75.108,23.952 r90 top
TP51 "TEST-Point" TP-1.0 115.3,20.559 r180 top
TP52 "TEST-Point" TP-1.0 83.972,56.896 r180 top
TP53 "TEST-Point" TP-1.0 84.363,23.266 r270 top
TP54 "TEST-Point" TP-1.0 86.106,56.896 r180 top
TP55 "TEST-Point" TP-1.0 78.638,58.369 r180 top
TP56 "TEST-Point" TP-1.0 75.625,58.471 r180 top
TP57 "TEST-Point" TP-1.0 77.902,51.918 r90 top
TP58 "TEST-Point" TP-1.0 73.295,52.365 r180 top
TP59 "TEST-Point" TP-1.0 115.037,69.147 r90 top
TP60 "TEST-Point" TP-1.0 115.037,71.628 r90 top
TP61 "TEST-Point" TP-1.0 115.265,24.13 r90 top
TP62 "TEST-Point" TP-1.0 98.18,45.255 r90 top
TP63 "TEST-Point" TP-1.0 102.892,39.834 r90 top
U1 "SPD1179" QFN-56-0.5_B 87.716,35.46 r180 top
U2 "LDO钰泰" ESOP-8_L4.9-W3.9-P1.27-LS6.0-BL-EP 108.915,58.293 r90 top
U3 "TJA1044GT/3" SOIC-8_L4.9-W3.9-P1.27-LS6.0-BL 108.144,43.242 r270 top
U4 "AD8542ARZ-REEL7" SOIC-8_L4.9-W3.9-P1.27-LS6.0-BL 101.332,12.344 r0 top
U5 "AD8542ARZ-REEL7" SOIC-8_L4.9-W3.9-P1.27-LS6.0-BL 90.078,12.344 r0 top
Y1 "32MHz" CRYSTAL-SMD_4P-L3.2-W2.5-BL 99.441,33.731 r90 top

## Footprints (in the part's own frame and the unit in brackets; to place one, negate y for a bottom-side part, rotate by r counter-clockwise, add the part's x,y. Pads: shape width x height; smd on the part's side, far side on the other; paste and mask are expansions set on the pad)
0805R [mm]
  rect 0.9x1.35 smd: 1(0,0) 2(1.9,0)
  silkscreen extent -0.75,-0.97 2.65,0.97
C0603 [mm]
  rect 0.95x1 smd: 1(-0.8,0) 2(0.8,0)
  silkscreen extent -1.73,-0.75 1.73,0.75
C1206 [mm]
  rect 1.15x1.8 smd: 1(-1.5,0) 2(1.5,0)
  silkscreen extent -2.51,-1.1 2.51,1.1
CAP-SMD_BD10.0-L10.3-W10.3-FD [mm]
  rect 4.5x1.65 smd: 1(-4.5,0) 2(4.5,0)
  silkscreen extent -5.23,-5.23 5.23,5.23
CON_63X08_P1 [mm] "Insert terminal"
  oval 4x2.5 hole 1 slot 2.5 at 0 deg: 1(0,0) 1(5,0)
  silkscreen extent -3.75,-3.3 8.8,3.3
CRYSTAL-SMD_4P-L3.2-W2.5-BL [mm]
  rect 1.4x1.2 smd: 1(-1.1,-0.85) 2(1.1,-0.85) 3(1.1,0.85) 4(-1.1,0.85)
  silkscreen extent -2.26,-1.91 2.03,1.68
ESOP-8_L4.9-W3.9-P1.27-LS6.0-BL-EP [mm]
  rect 0.6x1.2 smd: 1(-1.905,-2.908) 2(-0.635,-2.908) 3(0.635,-2.908) 4(1.905,-2.908) 5(1.905,2.908) 6(0.635,2.908) 7(-0.635,2.908) 8(-1.905,2.908)
  rect 3.3x2.4 smd: 9(0,0)
  silkscreen extent -3.2,-2.67 2.55,2.05
HDR1X2 [mm] "Connector; Header; 2 Position"
  rect 1.5x1.5 hole 0.9: 1(0,0)
  round 1.5 hole 0.9: 2(2.54,0)
  silkscreen extent -1.27,-1.27 3.81,1.27
HDR1X3 [mm] "Connector; Header; 3 Position"
  rect 1.5x1.5 hole 0.9: 1(0,0)
  round 1.5 hole 0.9: 2(2.54,0) 3(5.08,0)
  silkscreen extent -1.27,-1.27 6.35,1.27
HDR1X6 [mm] "Connector; Header; 6 Position"
  rect 1.5x1.5 hole 0.9: 1(0,0)
  round 1.5 hole 0.9: 2(2.54,0) 3(5.08,0) 4(7.62,0) 5(10.16,0) 6(12.7,0)
  silkscreen extent -1.27,-1.27 13.97,1.27
HDR2X2 [mm] "Connector; Header; 2x2 Position"
  rect 1.5x1.5 hole 0.9: 1(0,0)
  round 1.5 hole 0.9: 2(0,2.54) 3(2.54,0) 4(2.54,2.54)
  silkscreen extent -1.27,-1.27 3.81,3.81
HDR2X5 [mm] "Connector; Header; 5x2 Position"
  rect 1.5x1.5 hole 0.9: 1(0,0)
  round 1.5 hole 0.9: 2(0,2.54) 3(2.54,0) 4(2.54,2.54) 5(5.08,0) 6(5.08,2.54) 7(7.62,0) 8(7.62,2.54) 9(10.16,0) 10(10.16,2.54)
  silkscreen extent -1.27,-1.27 11.43,3.81
HDR2X7 [mm] "Connector; Header; 7x2 Position"
  rect 1.5x1.5 hole 0.9: 1(0,0)
  round 1.5 hole 0.9: 2(0,2.54) 3(2.54,0) 4(2.54,2.54) 5(5.08,0) 6(5.08,2.54) 7(7.62,0) 8(7.62,2.54) 9(10.16,0) 10(10.16,2.54) 11(12.7,0) 12(12.7,2.54) 13(15.24,0) 14(15.24,2.54)
  silkscreen extent -1.27,-1.27 16.51,3.81
HDR2X9 [mm] "Connector; Header; 9x2 Position"
  rect 1.5x1.5 hole 0.9: 1(0,0)
  round 1.5 hole 0.9: 2(0,2.54) 3(2.54,0) 4(2.54,2.54) 5(5.08,0) 6(5.08,2.54) 7(7.62,0) 8(7.62,2.54) 9(10.16,0) 10(10.16,2.54) 11(12.7,0) 12(12.7,2.54) 13(15.24,0) 14(15.24,2.54) 15(17.78,0) 16(17.78,2.54) 17(20.32,0) 18(20.32,2.54)
  silkscreen extent -1.27,-1.27 21.59,3.81
IND-SMD_4P-L4.5-W3.2-TL [mm]
  rect 1.4x0.899 smd mask+0: 1(-2.281,1.25) 2(-2.281,-1.25) 3(2.281,-1.25) 4(2.281,1.25)
  silkscreen extent -2.2,-1.6 2.2,1.6
IND-SMD_L12.6-W13.5 [mm]
  rect 4.6x5 smd paste+0 mask+0: 1(-6,0) 2(6,0)
  silkscreen extent -7.1,-6.6 7.1,6.6
KEY-TH_4P-L6.0-W6.0-P3.90-LS6.5 [mm]
  round 2 hole 1.2: 1(-3.25,1.95) 2(3.25,1.95) 3(-3.25,-1.95) 4(3.25,-1.95)
  silkscreen extent -3,-3 3,3
LED0603-R-RD [mm]
  rect 0.8x0.8 smd: 1(0.851,0) 2(-0.851,0)
  silkscreen extent -2.08,-0.86 1.77,0.86
PowerPAK_SO-8L_3_VIS [mil]
  rect 21x60 smd paste+0 mask+0: 1(-75,-142) 2(-25,-142) 3(25,-142) 4(75,-142)
  rect 162x193 smd paste+0 mask+0: 5(0,44.5)
  Top Layer lines w10: 0,44.5 0,34 ; 0,21.75 0,29.75 ; -67.25,80 -33.75,80 -0.25,80 0,80 33.25,80 66.75,80 50,63.25 16.5,63.25 0,63.25 -17,63.25 -38,63.25 -50.5,50.75 -67.25,34 -33.75,34 -0.25,34 0,34 ; 0,34 33.25,34 54.25,34 50,29.75 33.25,29.75 0,29.75 ; 0,34 0,29.75 ; 0,29.75 -0.25,29.75 -13.01,29.75 -27.5,15.25 -50.5,-7.75 -67.25,-24.5 -33.75,-24.5 -0.25,-24.5 0,-24.5 33.25,-24.5 54.25,-24.5 43.75,-14 4,25.75 0,29.75 ; 0,29.75 0,29.75 ; 0,29.75 0,29.75 ; 0,29.75 0,29.75
  silkscreen extent -104,-93 104,93
QFN-56-0.5_B [mm] "按高发封装修改意见"
  oval 1x0.25 smd: 1(0,0) 2(0,-0.5) 3(0,-1) 4(0,-1.5) 5(0,-2) 6(0,-2.5) 7(0,-3) 8(0,-3.5) 9(0,-4) 10(0,-4.5) 11(0,-5) 12(0,-5.5) 13(0,-6) 14(0,-6.5) 29(8.3,-6.5) 30(8.3,-6) 31(8.3,-5.5) 32(8.3,-5) 33(8.3,-4.5) 34(8.3,-4) 35(8.3,-3.5) 36(8.3,-3) 37(8.3,-2.5) 38(8.3,-2) 39(8.3,-1.5) 40(8.3,-1) 41(8.3,-0.5) 42(8.3,0)
  oval 0.25x1 smd: 15(0.9,-7.4) 16(1.4,-7.4) 17(1.9,-7.4) 18(2.4,-7.4) 19(2.9,-7.4) 20(3.4,-7.4) 21(3.9,-7.4) 22(4.4,-7.4) 23(4.9,-7.4) 24(5.4,-7.4) 25(5.9,-7.4) 26(6.4,-7.4) 27(6.9,-7.4) 28(7.4,-7.4) 43(7.4,0.9) 44(6.9,0.9) 45(6.4,0.9) 46(5.9,0.9) 47(5.4,0.9) 48(4.9,0.9) 49(4.4,0.9) 50(3.9,0.9) 51(3.4,0.9) 52(2.9,0.9) 53(2.4,0.9) 54(1.9,0.9) 55(1.4,0.9) 56(0.9,0.9)
  rect 6.2x6.2 smd: 57(4.15,-3.25)
  rect 8x8 smd far side: 57(4.15,-3.25)
  silkscreen extent -0.55,-7.45 8.35,1.36
R0402 [mm] "Resistor,Chip;1.00mm L X 0.50mm W"
  rect 0.59x0.64 smd: 1(-0.48,0) 2(0.48,0)
  silkscreen extent -0.95,-0.55 0.95,0.55
R0603 [mm] "Resistor,Chip;1.60mm L X 0.80mm W"
  rect 0.95x1 smd: 1(-0.8,0) 2(0.8,0)
  silkscreen extent 0,-0.5 0,0.5
R1206 [mm] "Chip Resistor; Body 3.2 x 1.6 mm (LxW typ)"
  rect 1.15x1.8 smd: 1(-1.5,0) 2(1.5,0)
  silkscreen extent -2.3,-1.1 2.3,1.1
R2512 [mm]
  rect 1.283x3.456 smd: 1(-3.066,0) 2(3.066,0)
  silkscreen extent -3.94,-1.96 3.94,1.96
"SCREW_HOLE_Φ3_plated_wo keepout" [mm] "with Spring  of Φ6.8mm"
  round 1 hole 1: 1(-2.5,0) 1(-1.768,-1.768) 1(-1.768,1.768) 1(0,-2.5) 1(0,2.5) 1(1.768,-1.768) 1(1.768,1.768) 1(2.5,0)
  round 6.8 hole 3.2: 1(0,0)
SMC/DO-214AB/Bidirect [mm]
  rect 3x3.8 smd: 1(3.301,0.102) 2(-3.649,0.112)
  silkscreen extent -3.27,-3.3 2.93,3.3
SOD-323_L1.7-W1.3-LS2.5-BI [mil]
  rect 31.5x31.5 smd mask+0: 1(-47.4,0) 2(47.4,0)
  silkscreen extent -34,-27 33,28
SOD-323_L1.8-W1.3-LS2.5-RD [mm]
  rect 1x0.75 smd: 1(-1.173,0) 2(1.173,0)
  silkscreen extent -0.85,-0.73 0.9,0.73
SODFL2513X100/SOD323F/SC-90 [mm]
  rect 0.84x0.46 smd: 1(-1.14,0) 2(1.14,0)
  silkscreen extent -2.03,-0.65 1.8,0.65
SOIC-8_L4.9-W3.9-P1.27-LS6.0-BL [mm]
  oval 0.588x2.045 smd: 1(-1.905,-2.773) 2(-0.635,-2.773) 3(0.635,-2.773) 4(1.905,-2.773) 5(1.905,2.773) 6(0.635,2.773) 7(-0.635,2.773) 8(-1.905,2.773)
  silkscreen extent -2.8,-2.92 2.53,1.52
SOT95P240X110-3/SOT23/TO-236 [mm]
  rect 1.05x0.8 smd: 1(-1.15,0.95) 2(-1.15,-0.95) 3(1.15,0)
  silkscreen extent -1.52,-1.45 0.3,1.92
SOT-23_L2.9-W1.3-P1.90-LS2.4-BR [mm]
  rect 1x0.8 smd mask+0: 1(1.15,-0.95) 2(1.15,0.95) 3(-1.15,0)
  silkscreen extent -0.7,-1.5 0.7,1.5
SOT-363_L2.0-W1.3-P0.65-LS2.1-TL [mm]
  rect 0.7x0.42 smd: 1(-0.92,0.65) 2(-0.92,0) 3(-0.92,-0.65) 4(0.92,-0.65) 5(0.92,0) 6(0.92,0.65)
  silkscreen extent -1.09,-1.1 0.7,1.24
TEST-SMD_L2.7-W1.0 [mm]
  rect 3.43x1.78 smd: 1(0,0)
TP-1.0 [mm]
  round 1 smd: 1(0,0)

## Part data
C1 C5 C6 C14 C15: library part CE_50V_220uF_10*10, "Capacitor polarized"
C2 C3 C10 C35 C38 C55: library part C_1206_10%_1, "MLCC"
C4 C7 C8 C9 C11 C12 C13 C16 C17 C18 C19 C20 C21 C22 C23 C24 C25 C26 C27 C28 C29 C30 C31 C32 C33 C34 C36 C37 C39 C40 C41 C42 C43 C44 C45 C46 C47 C48 C49 C50 C51 C52 C53 C54 C56 C57 C58 C59 C60 C61 C62 C63 C64 C65 C66 C67 C68 C69 C70 C71 C72 C73 C74 C75 C76 C77 C78 C79 C80 C81 C82 C83 C84 C85 C86 C87 C90: library part C_0603_10%_1, "MLCC"
D1: library part D_TVS_SMC, "TVS Bidirectional"
D2 D3 D4 D5 D6 D7 D8 D9 D10 D11 D16: library part D_1N4148WS, "Diode SOD323"
D12: library part D_SMA, "Diode"
D15: library part D_PESD1CAN,215
D18: library part D_ESD_BI_SOD323, "ESD TVS Bidirectional"
JP2: library part Jumper, "Jumper Wire"
L1: library part L_SER2000
L2: library part L_ACT45B-510-2P-TL003
P1 P6 P14 P15 P16: "Insert terminal,快接端子 6.3mm*0.8厚 插片"
P2: "Header, 9-Pin, Dual row"
P3: "Header, 6-Pin"
P4 P8 P11: library part "Header 2", "Header, 2-Pin"
P5 P9: "Header, 7-Pin, Dual row"
P7: "Header, 5-Pin, Dual row"
P10 P12: "Header, 3-Pin"
P23: "Header, 2-Pin, Dual row"
P25: "Header, 2-Pin"
Q1 Q3 Q4 Q5 Q6 Q7 Q8: library part Q_N_DFN-8L_5*6, "N-CHANNEL"
Q2 Q10: library part Q_8050
Q9: library part Q_BC847BPN,115
Q11: library part Q_BSS138, "N-CHANNEL"
R1 R2 R3 R5 R6 R7 R8 R9 R10 R11 R12 R13 R14 R15 R16 R17 R18 R19 R20 R21 R22 R23 R24 R25 R26 R27 R28 R29 R30 R31 R34 R35 R36 R38 R39 R40 R41 R42 R44 R48 R49 R50 R54 R56 R57 R58 R60 R61 R62 R63 R64 R65 R66 R68 R69 R70 R71 R72 R73 R74 R75 R76 R77 R78 R79 R80 R81 R82 R84 R85 R86 R87 R88 R89 R90 R91 R92 R93 R94 R95 R96 R97 R98 R99 R100 R102 R103 R104 R105 R106 R107 R108 R110 R111 R112 R113 R114 R115 R116 R117 R118 R119 R120 R121 R122 R123 R125 R126: library part R_0603_1/10W_1%_1, "Thick film"
R4 R32 R33 R37 R43 R45 R46 R47 R83: library part R_1206_1/4W_1%_1, "Thick film"
R51 R52 R53 R55: library part R_2512_1, "Thick film"
R59 R67: library part R_0402_1/16W_1%_1, "Thick film"
R109: library part R_NTC_5R_2A_P5mm, "10kΩ 电阻精度:±0.5% 3380K  NTCG163JX103DT1S"
SW1: library part SW_TH_4P_L6.0W6.0_P3.9_LS6.5, "TH 3.9*6.5"
TP40: "测试点/测试环,5017"
U1: library part U_SPD1179_QFN56, "32-bit ARM CM4 automotives MCU with HV power management, LIN and PDRV"
U2: library part U_LDO_EQ5430
U3: library part U_TJA1044GT/3, "CAN transceiver CAN FD"
U4 U5: library part U_LM2904DT
Y1: library part Z_32MHz_SMD

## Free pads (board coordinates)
  round 10 hole 4.5: 1(5.918,16.042) 1(5.918,31.017) 1(5.918,45.993) 1(5.918,63.932) 1(5.918,76.784)

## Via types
v1: diameter 0.7, hole 0.3, Top Layer to Bottom Layer, tented both sides, 810 vias
v2: diameter 0.5, hole 0.2, Top Layer to Bottom Layer, tented both sides, 161 vias
v3: diameter 0.9, hole 0.5, Top Layer to Bottom Layer, 60 vias
v4: diameter 0.6, hole 0.3, Top Layer to Bottom Layer, tented top, 25 vias

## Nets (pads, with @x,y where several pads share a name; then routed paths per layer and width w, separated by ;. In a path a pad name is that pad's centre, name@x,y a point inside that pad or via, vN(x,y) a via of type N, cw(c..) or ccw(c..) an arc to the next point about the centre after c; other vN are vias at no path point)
1.65V: C65.1 C66.1 C74.2 C82.1 R76.1 R77.1 R95.1 R110.1 TP35.1 | length 29.9
  Top Layer w0.254: R95.1@94.904,11.138 C82.1@96.987,11.138 C74.2@96.987,13.297 ; R110.1@94.904,14.897 R110.1@94.929,14.897 ; TP35.1@95.996,21.488 95.996,15.989 95.277,15.27 95.277,15.245 R110.1@94.929,14.897 ; C66.1@108.687,11.138 R77.1@106.705,11.138 R76.1@106.705,13.297 ; C65.1@108.687,13.297 R76.1@106.705,13.297 ; R110.1@94.929,14.897 96.181,13.645 96.639,13.645 C74.2@96.987,13.297 ; C74.2@96.987,13.297 R76.1@106.705,13.297
5V_COM: C44.2 C58.2 P4.1 P4.2 R50.2 U2.1 U3.3 | length 48.6
  Top Layer w0.254: C44.2@115.532,56.49 116.567,57.525 117.151,57.525 118.11,58.484 R50.2@118.135,58.484
  Top Layer w0.508: v1(100.608,47.252) 100.608,51.51 104.11,55.012 115.526,55.012 ; C58.2@101.704,43.222 101.704,43.197 101.729,43.222 v1(103.473,43.222) 104.073,42.623 105.356,42.623 U3.3@105.371,42.607 ; U2.1@111.823,56.388 112.123,56.388 112.225,56.49 C44.2@115.532,56.49 115.532,55.018 115.526,55.012 ; P4.1@122.098,59.944 P4.2@122.098,57.404 119.705,55.012 115.526,55.012
  Bottom Layer w0.508: v1(100.608,47.252) 100.608,46.087 v1(103.473,43.222)
ADC0: R30.2 U1.52 | length 27.7
  Top Layer w0.254: U1.52@84.816,34.56 84.816,33.044 85.373,32.487 85.948,32.487 86.362,32.073 91.879,32.073 93.54,30.412 93.54,26.517 95.184,24.872 99.606,24.872 101.516,22.962 R30.2@104.572,22.962
ADC1: R29.2 U1.53 | length 26.4
  Top Layer w0.254: U1.53@85.316,34.56 85.316,33.206 85.563,32.959 86.118,32.959 86.55,32.527 92.072,32.527 93.997,30.601 93.997,26.706 95.374,25.33 99.883,25.33 100.676,24.536 R29.2@104.521,24.536
ADC2: R28.2 U1.54 | length 24.8
  Top Layer w0.254: U1.54@85.816,34.56 85.816,33.609 86.009,33.416 86.303,33.416 86.738,32.981 92.264,32.981 94.454,30.791 94.454,27.101 95.203,26.352 R28.2@104.508,26.352
ADC3: R1.2 R10.2 U1.55 | length 17.4
  Top Layer w0.254: U1.55@86.316,34.56 86.318,34.558 86.318,34.043 86.734,33.627 92.102,33.627 v1(92.132,33.658) 94.758,33.658 R1.2@94.882,33.782 ; v1(95.278,29.591) 95.278,28.819 96.639,27.458 R10.2@96.639,27.433
  Bottom Layer w0.254: v1(92.132,33.658) 92.132,32.737 v1(95.278,29.591)
ADC4: R8.2 R120.2 U1.56 | length 18
  Top Layer w0.254: U1.56@86.816,34.56 U1.56@86.816,34.56 v1@91.98,34.558 ; v1(92.168,34.557) 94.031,34.557 94.882,35.408 R120.2@94.882,35.433 ; v1(96.59,30.202) 96.59,29.103 R8.2@96.629,29.064
  Bottom Layer w0.254: v1(92.168,34.557) 92.998,35.387 94.224,35.387 96.59,33.021 v1(96.59,30.202)
ADC5: R102.2 U1.1 | length 27
  Top Layer w0.254: U1.1@87.716,35.46 90.956,35.46 92.489,36.992 92.489,37.96 93.701,39.172 94.005,39.172 v1(94.09,39.258) ; v1(102.067,29.435) 102.067,30.372 103.467,31.772 R102.2@103.467,31.797
  L3 w0.254: v1@94.005,39.172 v1(94.09,39.258) 94.09,34.471 99.875,28.686 101.319,28.686 v1(102.067,29.435)
ADC6: R87.2 U1.2 | length 27.6
  Top Layer w0.254: U1.2@87.716,35.96 90.814,35.96 92.032,37.177 92.032,38.156 93.876,40.001 94.517,40.001 94.756,39.762 95.341,39.762 v1(95.426,39.676) ; v1(100.492,29.741) 102.285,31.533 102.285,33.107 102.674,33.496 R87.2@103.481,33.496
  L3 w0.254: v1(95.426,39.676) 95.467,39.635 95.467,34.766 v1(100.492,29.741)
ADC7: R78.2 U1.3 | length 20.2
  Top Layer w0.254: U1.3@87.716,36.46 90.672,36.46 91.578,37.365 91.578,38.344 93.688,40.455 94.869,40.455 94.971,40.353 95.739,40.353 95.961,40.131 96.675,40.131 v1(96.692,40.114) 96.692,39.44 96.813,39.319 100.487,39.319 100.909,38.896 101.427,38.896 102.9,37.424 R78.2@104.034,37.424
ADC8: R61.2 U1.4 | length 35.8
  Top Layer w0.254: U1.4@87.716,36.96 89.582,36.96 89.782,37.159 90.355,37.159 v1(90.44,37.244) ; v1(98.041,40.042) 98.08,40.003 100.793,40.003 101.419,39.377 101.95,39.377 102.92,38.407 106.346,38.407 107.372,39.432 v1(114.464,39.432) ; v1(115.612,37.08) 117.712,34.979 R61.2@117.712,34.954
  L3 w0.254: v1(90.44,37.244) 93.306,40.11 93.968,40.11 94.943,41.084 96.998,41.084 v1(98.041,40.042) ; v1(114.464,39.432) 114.464,38.227 v1(115.612,37.08)
BOOT: P5.2 R11.2 U1.5 | length 81.7
  Top Layer w0.254: U1.5@87.716,37.46 89.416,37.46 90.144,38.188 90.427,38.188 v1(91.045,38.807) v1@91.045,38.776 ; v1(97.109,51.833) 97.109,54.833 96.901,55.041 96.901,62.183 99.959,65.242 106.974,65.242 109.477,67.745 113.104,67.745 113.634,68.275 v1(122.352,68.275) ; R11.2@122.652,83.897 124.138,83.897 P5.2@128.626,79.41
  Bottom Layer w0.254: v1(91.045,38.807) 91.076,38.807 92.833,40.564 94.236,40.564 95.208,41.536 95.208,46.165 95.759,46.716 95.759,50.482 v1(97.109,51.833) ; v1(122.352,68.275) 122.352,75.565 124.917,78.13 127.346,78.13 P5.2@128.626,79.41
CANH: L2.1 R59.1 TP29.1 U3.7 | length 9.7
  Top Layer w0.508: U3.7@110.916,43.877 110.932,43.893 112.587,43.893 113.096,44.402 113.096,45.495 TP29.1@113.191,45.589 113.191,45.691 114.54,47.041 116.813,47.041 117.408,47.636 117.408,48.553 R59.1@117.449,48.594
CANL: L2.2 R67.1 TP31.1 U3.6 | length 9.8
  Top Layer w0.508: U3.6@110.916,42.607 110.926,42.616 114.066,42.616 TP31.1@114.075,42.626 114.072,42.629 114.075,42.632 114.075,43.947 114.775,44.647 L2.2@116.668,44.647 116.864,44.452 117.492,44.452 118.532,43.412 R67.1@118.532,43.387
CANLDOEN: R81.1 TP30.1 U1.22 | length 45.5
  Top Layer w0.254: U1.22@83.316,42.86 83.316,44.677 84.11,45.471 v1(84.11,47.041) ; TP30.1@98.958,60.808 100.394,60.808 R81.1@100.622,60.579 100.622,60.554 101.362,59.814 101.362,59.471 v1(101.448,59.385) ; v1(102.275,51.265) 104.155,53.145 104.155,53.843 v1(104.188,53.876)
  L3 w0.254: v1(84.11,47.041) 85.739,45.413 103.694,45.413 104.853,46.572 104.853,48.687 v1(102.275,51.265)
  Bottom Layer w0.254: v1(101.448,59.385) 104.188,56.645 v1(104.188,53.876)
CANRX: R65.2 R116.1 TP63.1 U1.24 | length 54.9
  Top Layer w0.254: U1.24@82.316,42.86 82.316,45.325 82.547,45.556 82.547,46.777 v1(82.773,47.003) ; v1(92.336,62.348) R116.1@92.336,63.483 ; v1@98.546,41.332 v1(98.55,41.336) R65.2@100.137,41.336 100.137,41.311 101.199,40.248 101.199,40.243 101.609,39.834 TP63.1@102.892,39.834
  L3 w0.254: v1@82.688,46.918 v1(82.773,47.003) 82.773,46.538 82.547,46.312 82.547,45.445 83.777,44.215 94.941,44.215 97.84,41.316 98.53,41.316 v1(98.55,41.336) ; v1(82.995,59.756) 86.148,59.756 88.22,61.828 91.816,61.828 v1(92.336,62.348)
  Bottom Layer w0.254: v1(82.773,47.003) 85.011,49.24 85.011,57.74 v1(82.995,59.756)
CANSTB: R79.1 TP48.1 U1.21 | length 36
  Top Layer w0.254: U1.21@83.816,42.86 83.816,44.356 84.611,45.151 84.611,46.367 84.985,46.741 84.985,47.155 v1(85.07,47.24) ; v1(101.741,47.286) 101.741,49.443 102.489,50.19 106.13,50.19 109.094,47.226 R79.1@109.094,47.201 109.129,47.236 110.332,47.236 110.545,47.45 110.545,48.214 TP48.1@110.663,48.331
  L3 w0.254: v1(85.07,47.24) 94.839,47.24 95.856,46.223 100.678,46.223 v1(101.741,47.286)
CANTX: R62.2 TP62.1 U1.23 | length 22.3
  Top Layer w0.254: U1.23@82.816,42.86 82.816,44.879 83.269,45.332 83.269,46 v1(83.332,46.063) ; v1(98.133,44.019) 98.157,44.043 98.157,45.231 TP62.1@98.18,45.255 100.097,45.255 R62.2@100.137,45.296
  L3 w0.254: v1(83.332,46.063) 84.514,44.881 97.271,44.881 v1(98.133,44.019)
CFBOT0: C50.1 TP41.1 U1.32 | length 11.1
  Top Layer w0.254: TP41.1@71.623,45.544 72.464,44.704 C50.1@73.53,44.704 73.53,44.679 74.386,43.823 75.604,43.823 75.667,43.76 76.886,43.76 77.633,43.013 77.633,41.127 77.615,41.109 78.265,40.46 U1.32@79.416,40.46
CFBOT1: C45.2 TP39.1 U1.34 | length 9.9
  Top Layer w0.254: TP39.1@71.637,43.409 71.839,43.409 72.271,42.977 C45.2@73.315,42.977 73.315,42.098 73.735,41.677 75.754,41.677 77.972,39.46 U1.34@79.416,39.46
CFTOP0: C50.2 TP43.1 U1.31 | length 7.1
  Top Layer w0.254: C50.2@75.206,44.628 C50.2@75.13,44.704 75.133,44.707 TP43.1@76.725,44.707 78.068,43.365 ; 78.087,43.365 78.087,41.284 78.411,40.96 U1.31@79.416,40.96
CFTOP1: C45.1 TP42.1 U1.33 | length 6.6
  Top Layer w0.254: C45.1@74.915,42.977 TP42.1@76.735,42.977 ; TP42.1@76.604,42.671 TP42.1@76.806,42.671 76.806,41.272 78.118,39.96 U1.33@79.416,39.96
D2SOUT: P2.10 R122.2 | length 17
  Top Layer w0.254: R122.2@112.89,27.33 119.318,27.33 120.474,26.174 127.495,26.174 128.626,25.043 P2.10@128.626,24.765
FB: R56.1 R57.2 U2.2 | length 4.8
  Top Layer w0.254: U2.2@111.823,57.658 112.123,57.658 112.936,58.471 R56.1@114.643,58.471 R57.2@114.643,60.096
